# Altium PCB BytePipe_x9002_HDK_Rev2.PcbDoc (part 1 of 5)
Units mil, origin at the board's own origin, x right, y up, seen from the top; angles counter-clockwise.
Board outline 4250 x 4250 mil, 8 copper layers (Top Layer, L2-GND, L3-SIG, L4-GND, L5-PWR, L6-SIG, L7-GND, Bottom Layer), stack 63 mil thick; 296 components, 250 nets, 1198 pads, 2326 vias.
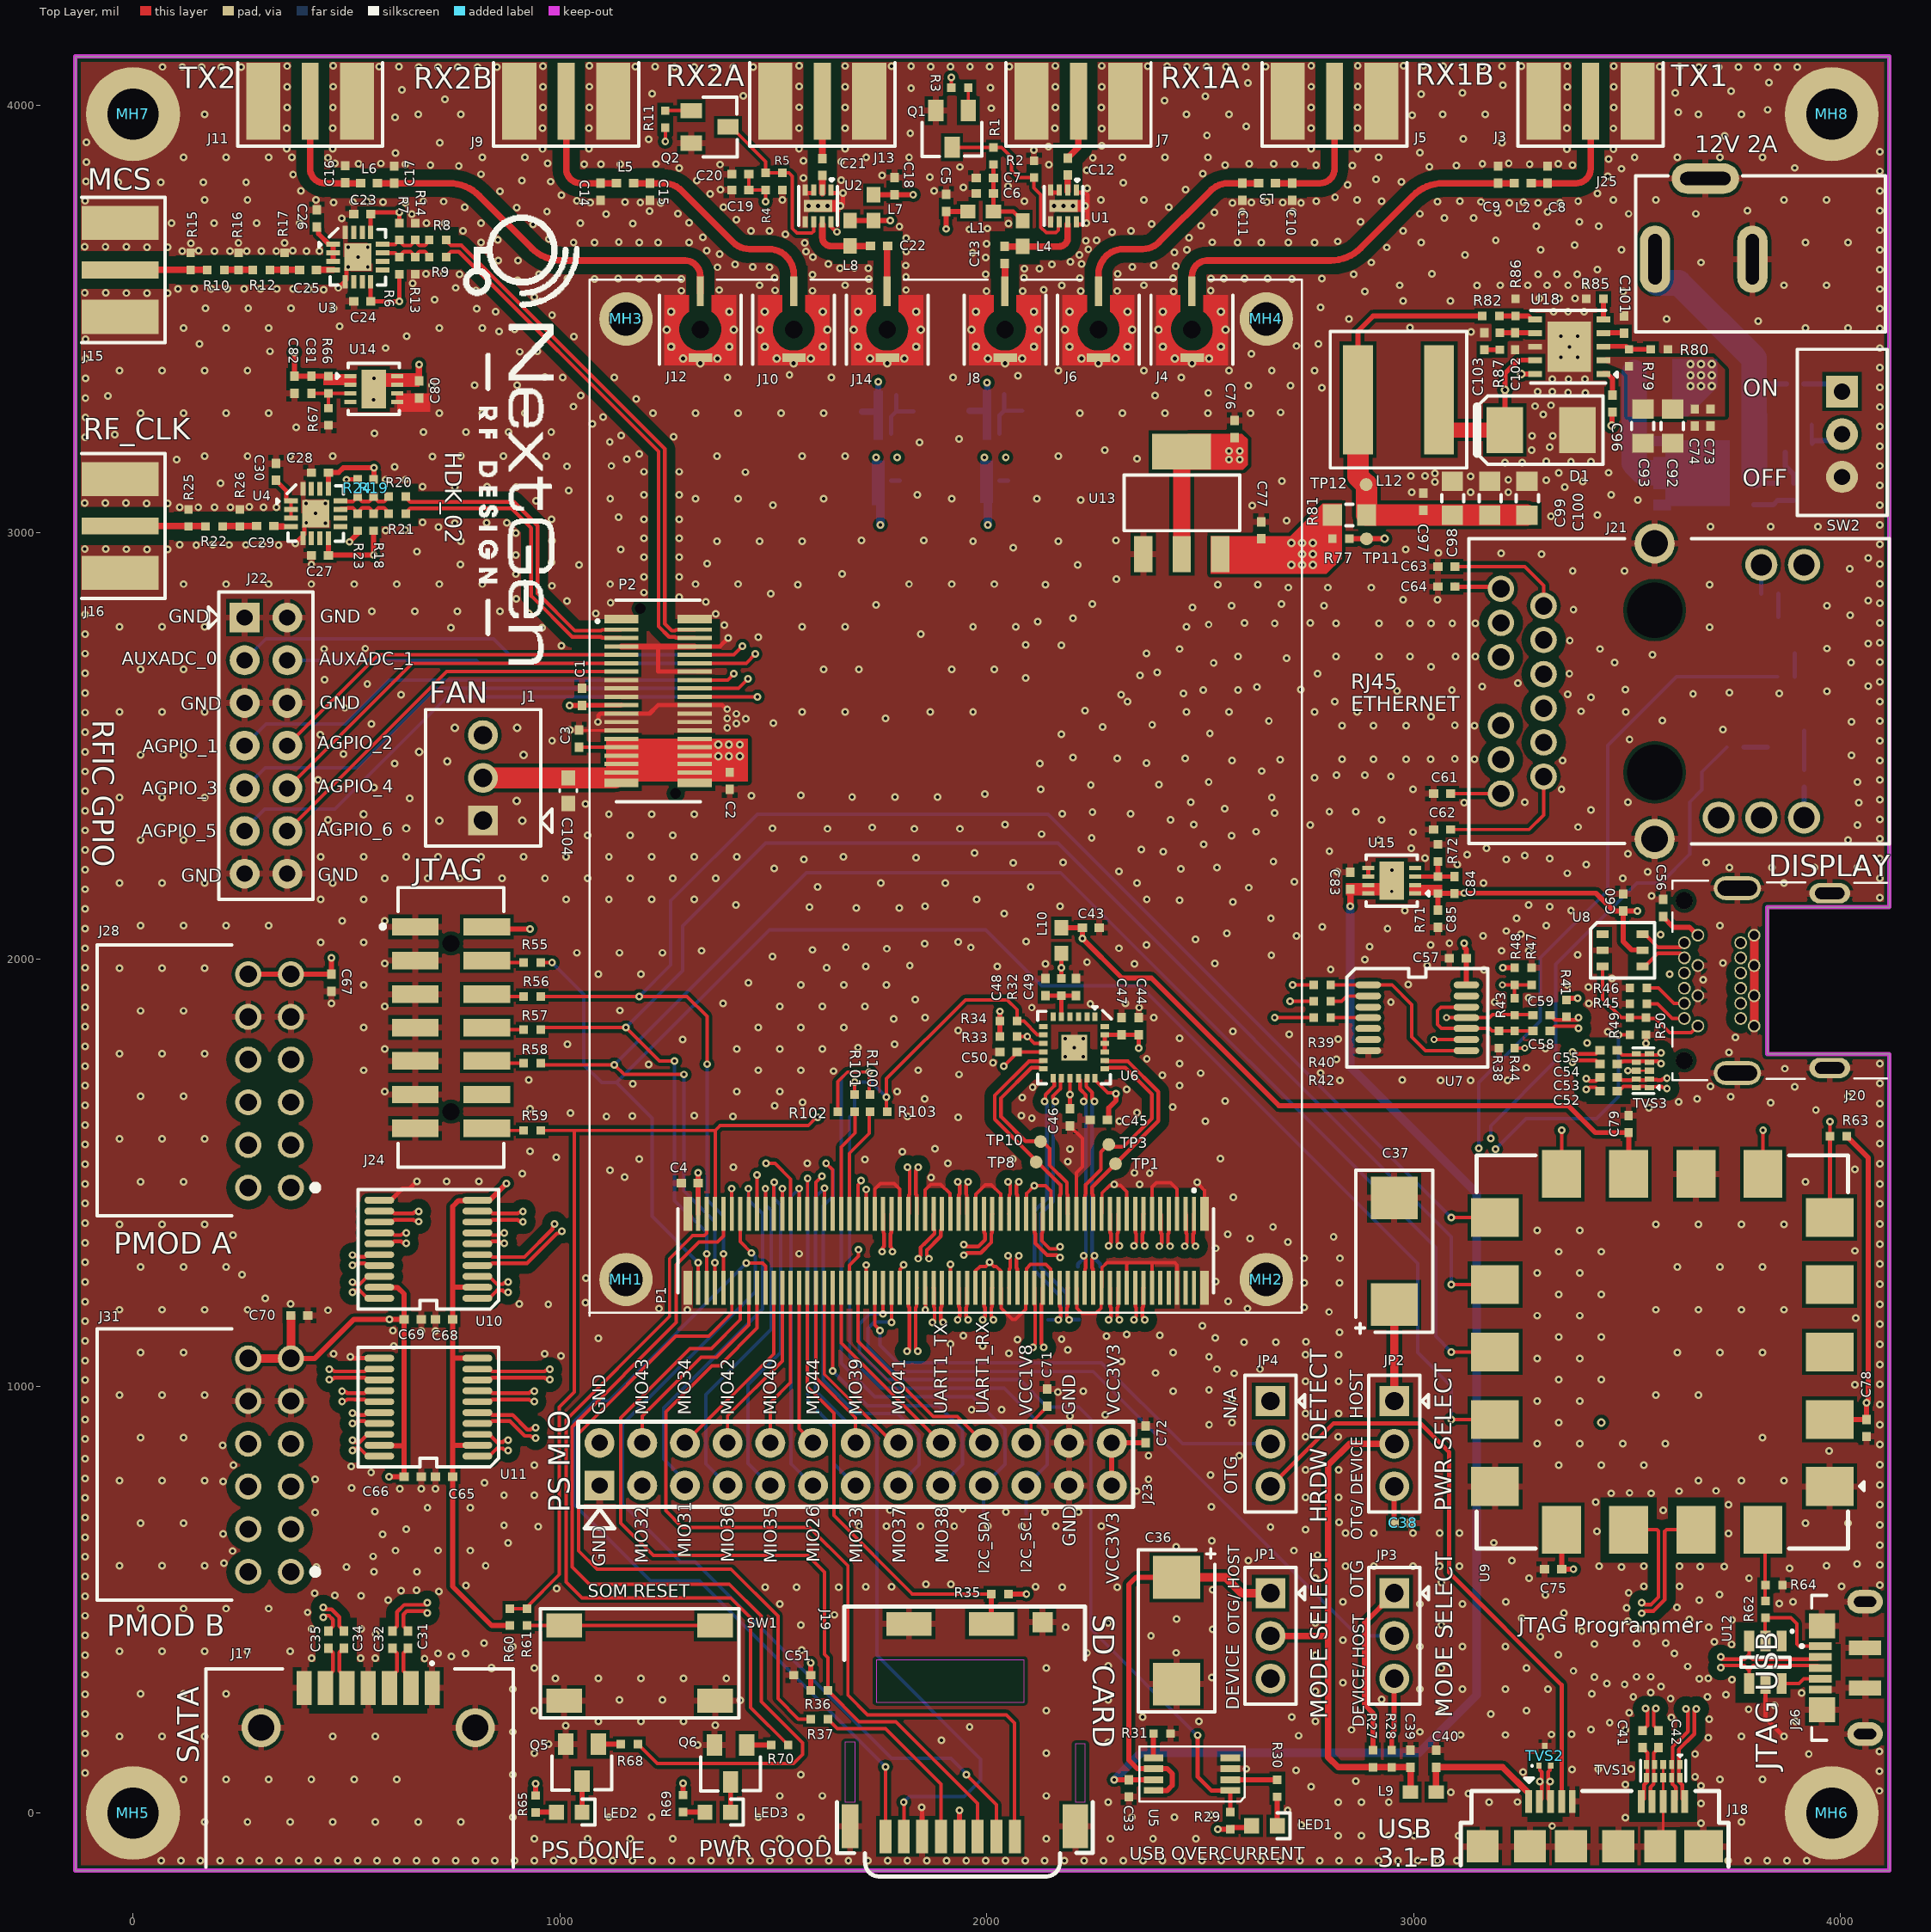
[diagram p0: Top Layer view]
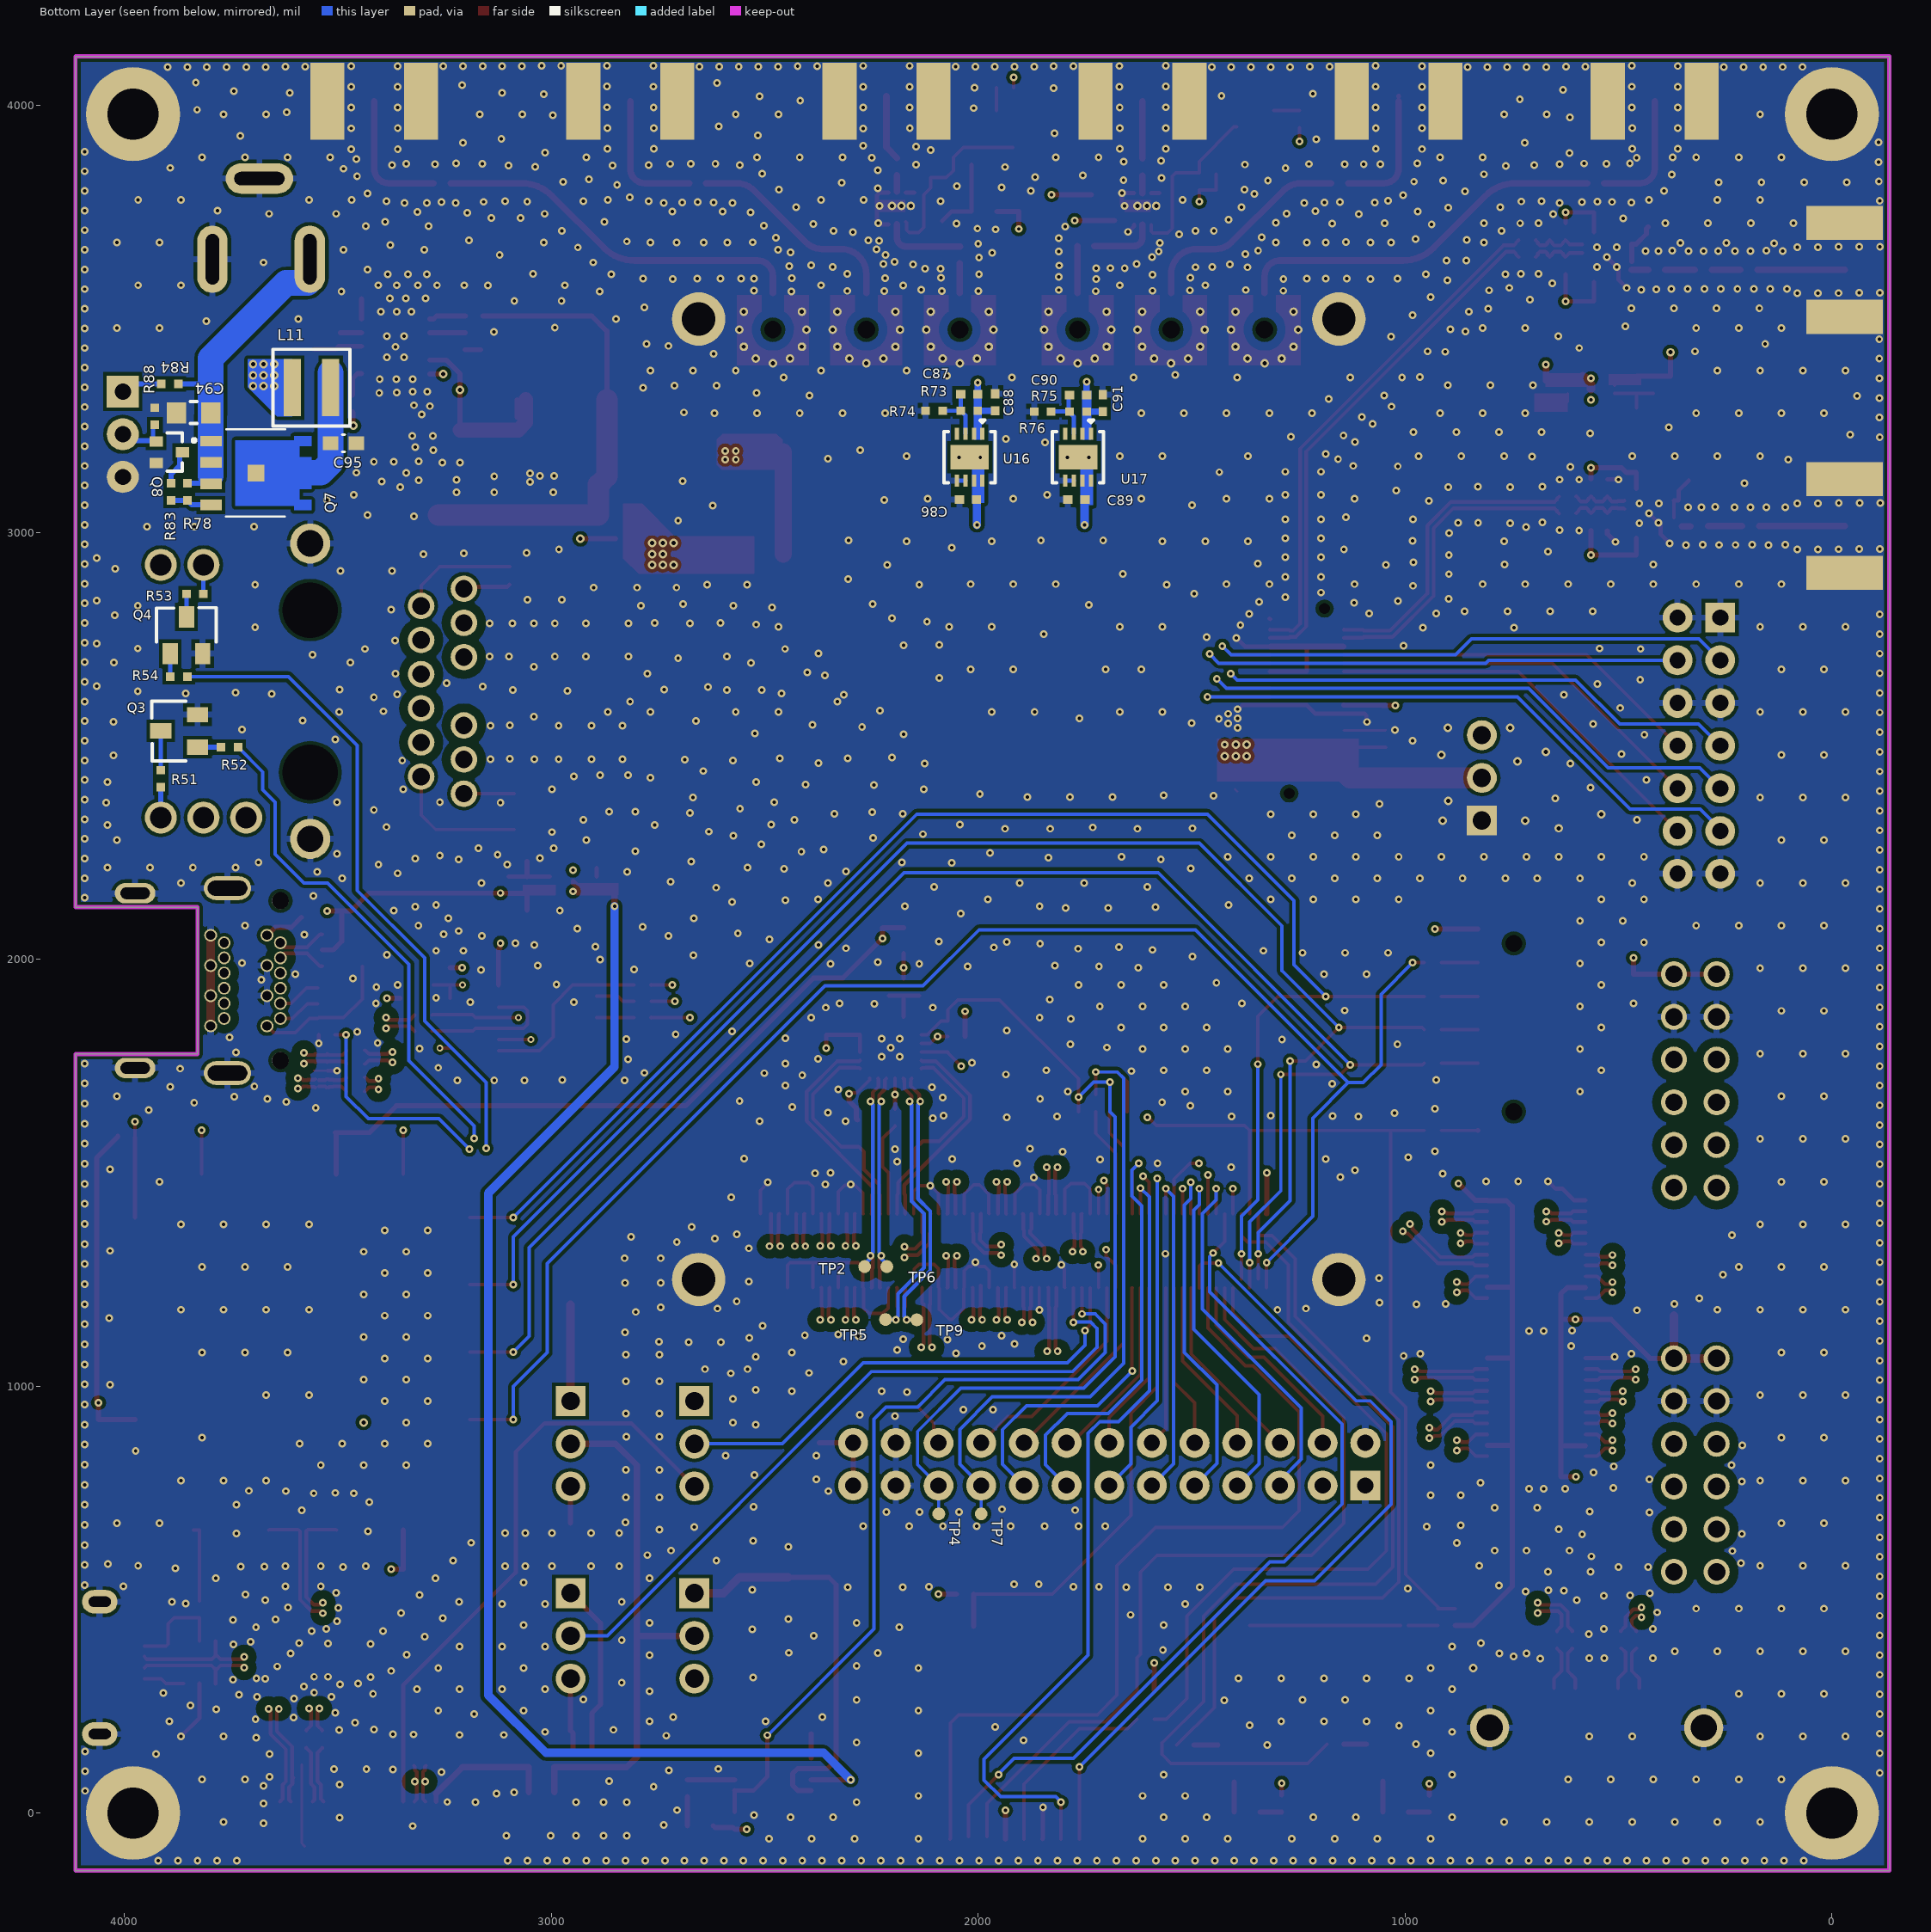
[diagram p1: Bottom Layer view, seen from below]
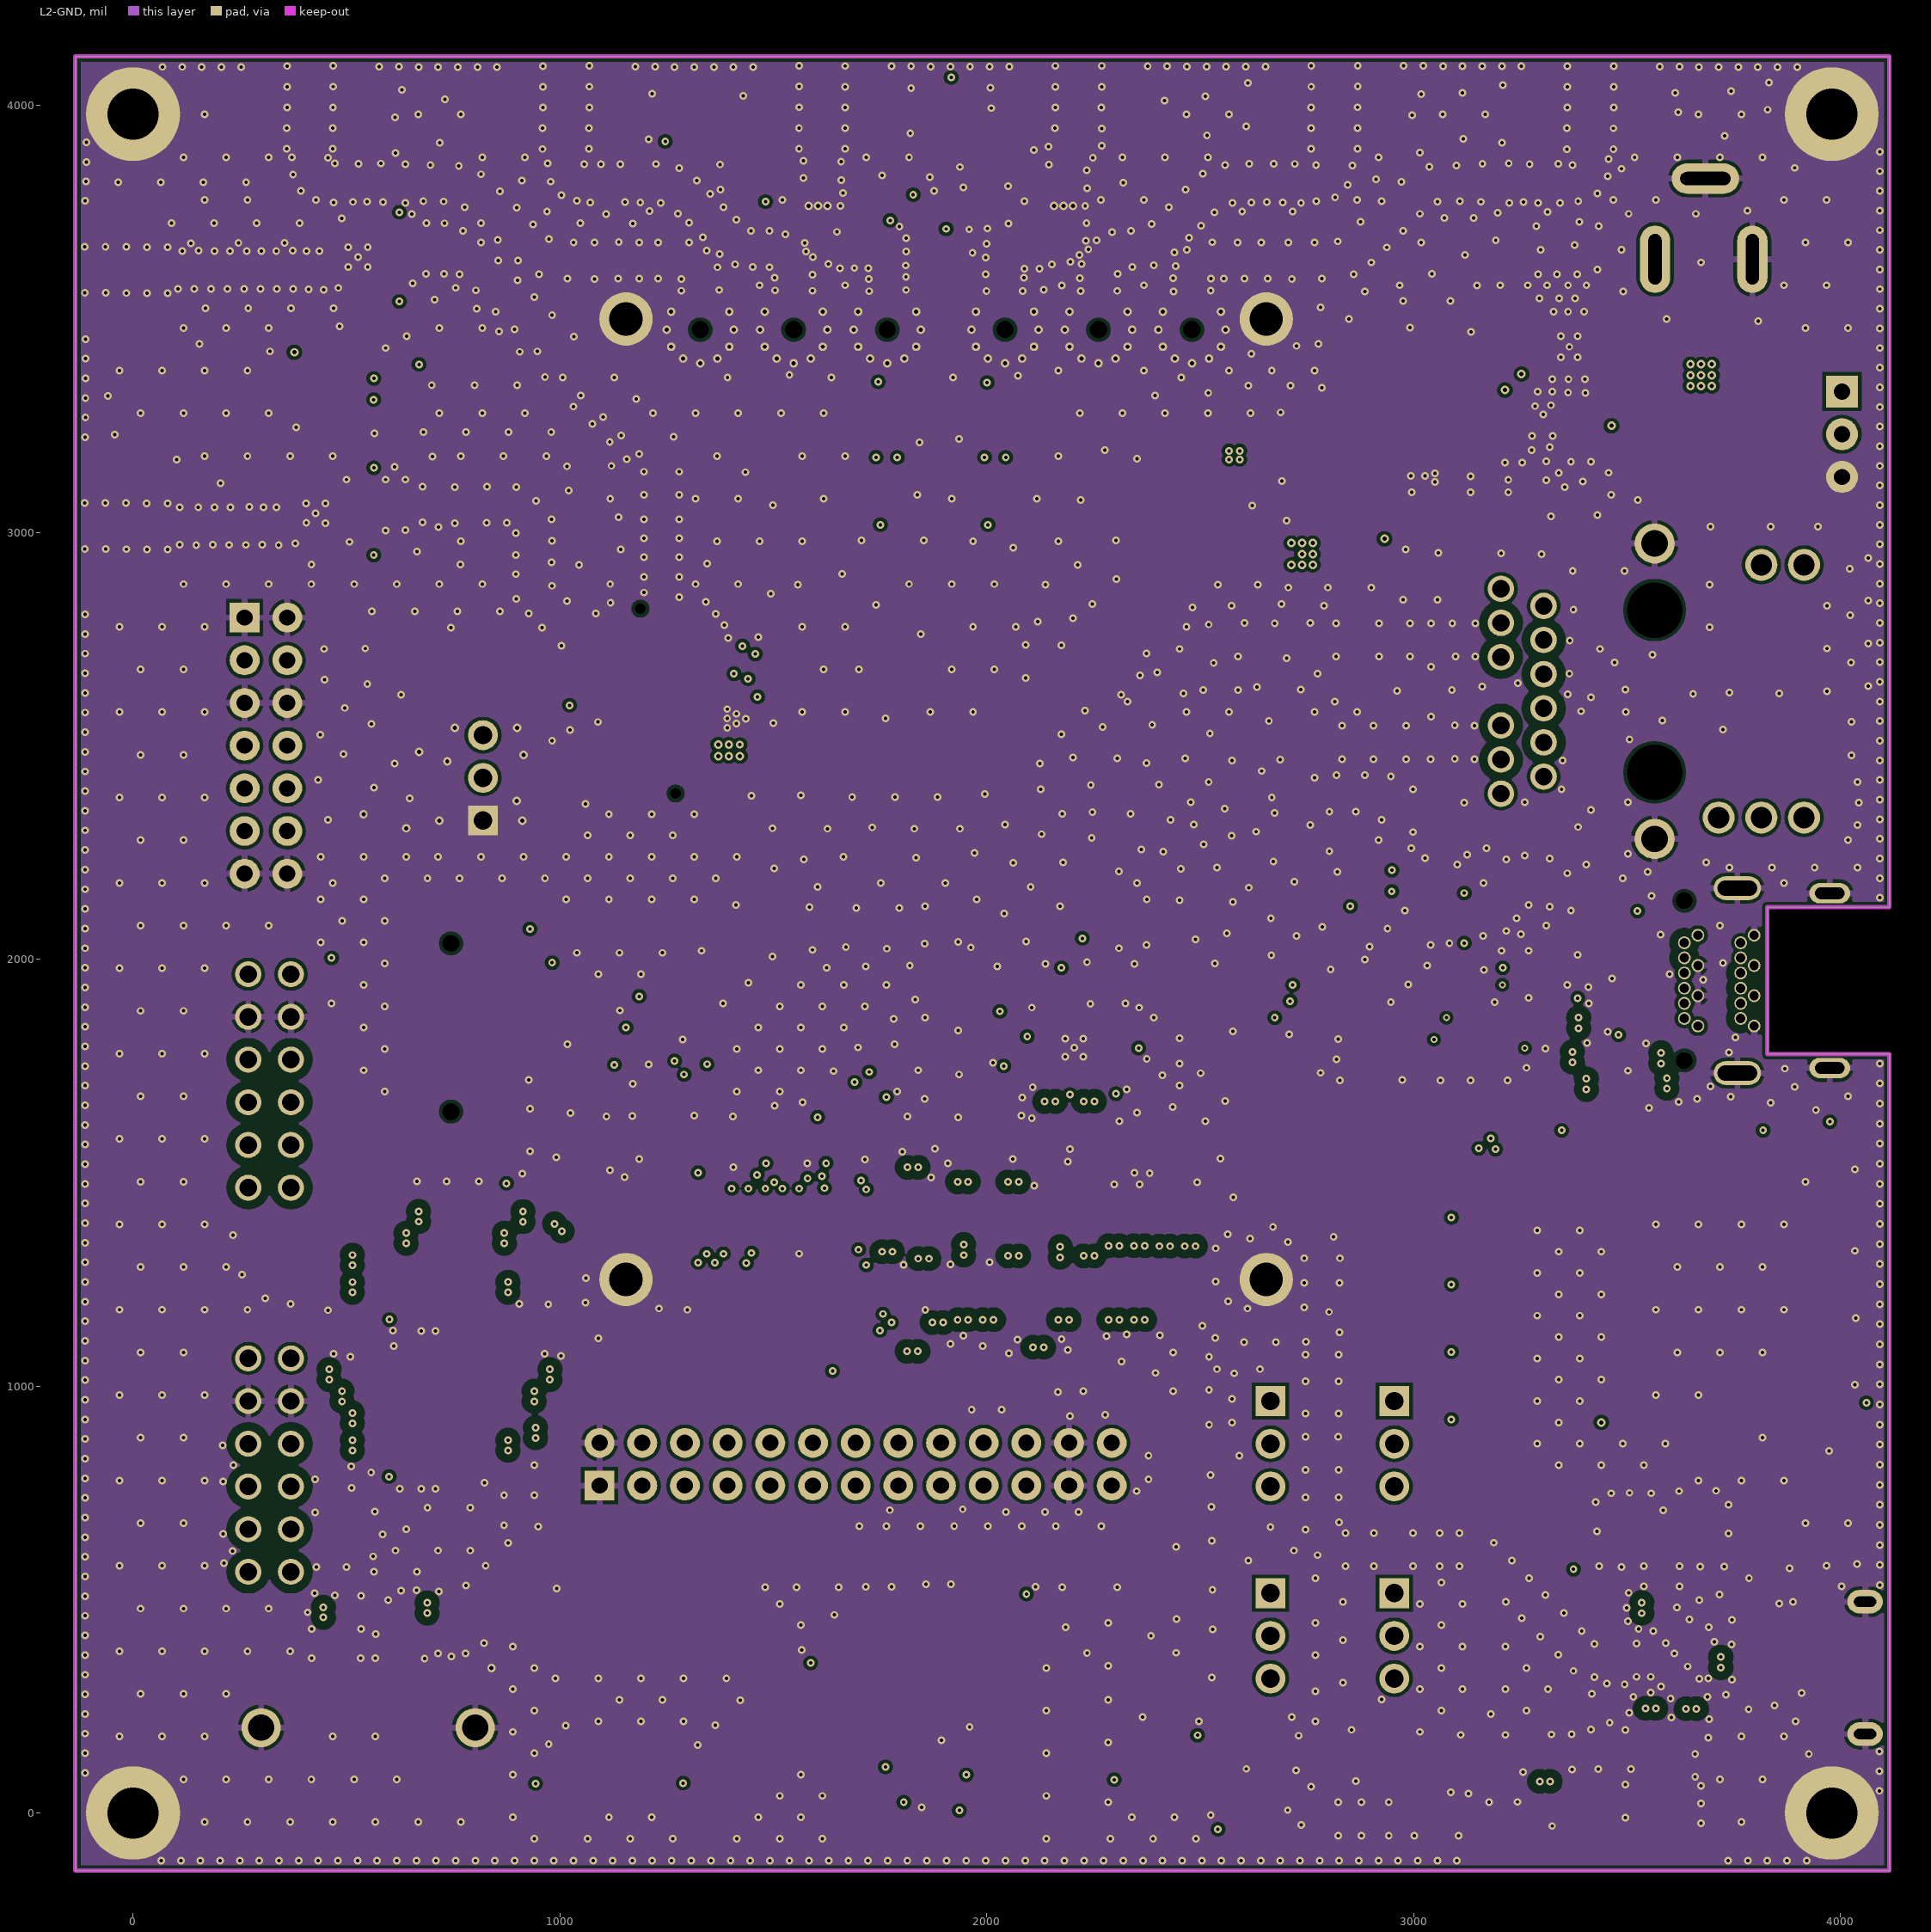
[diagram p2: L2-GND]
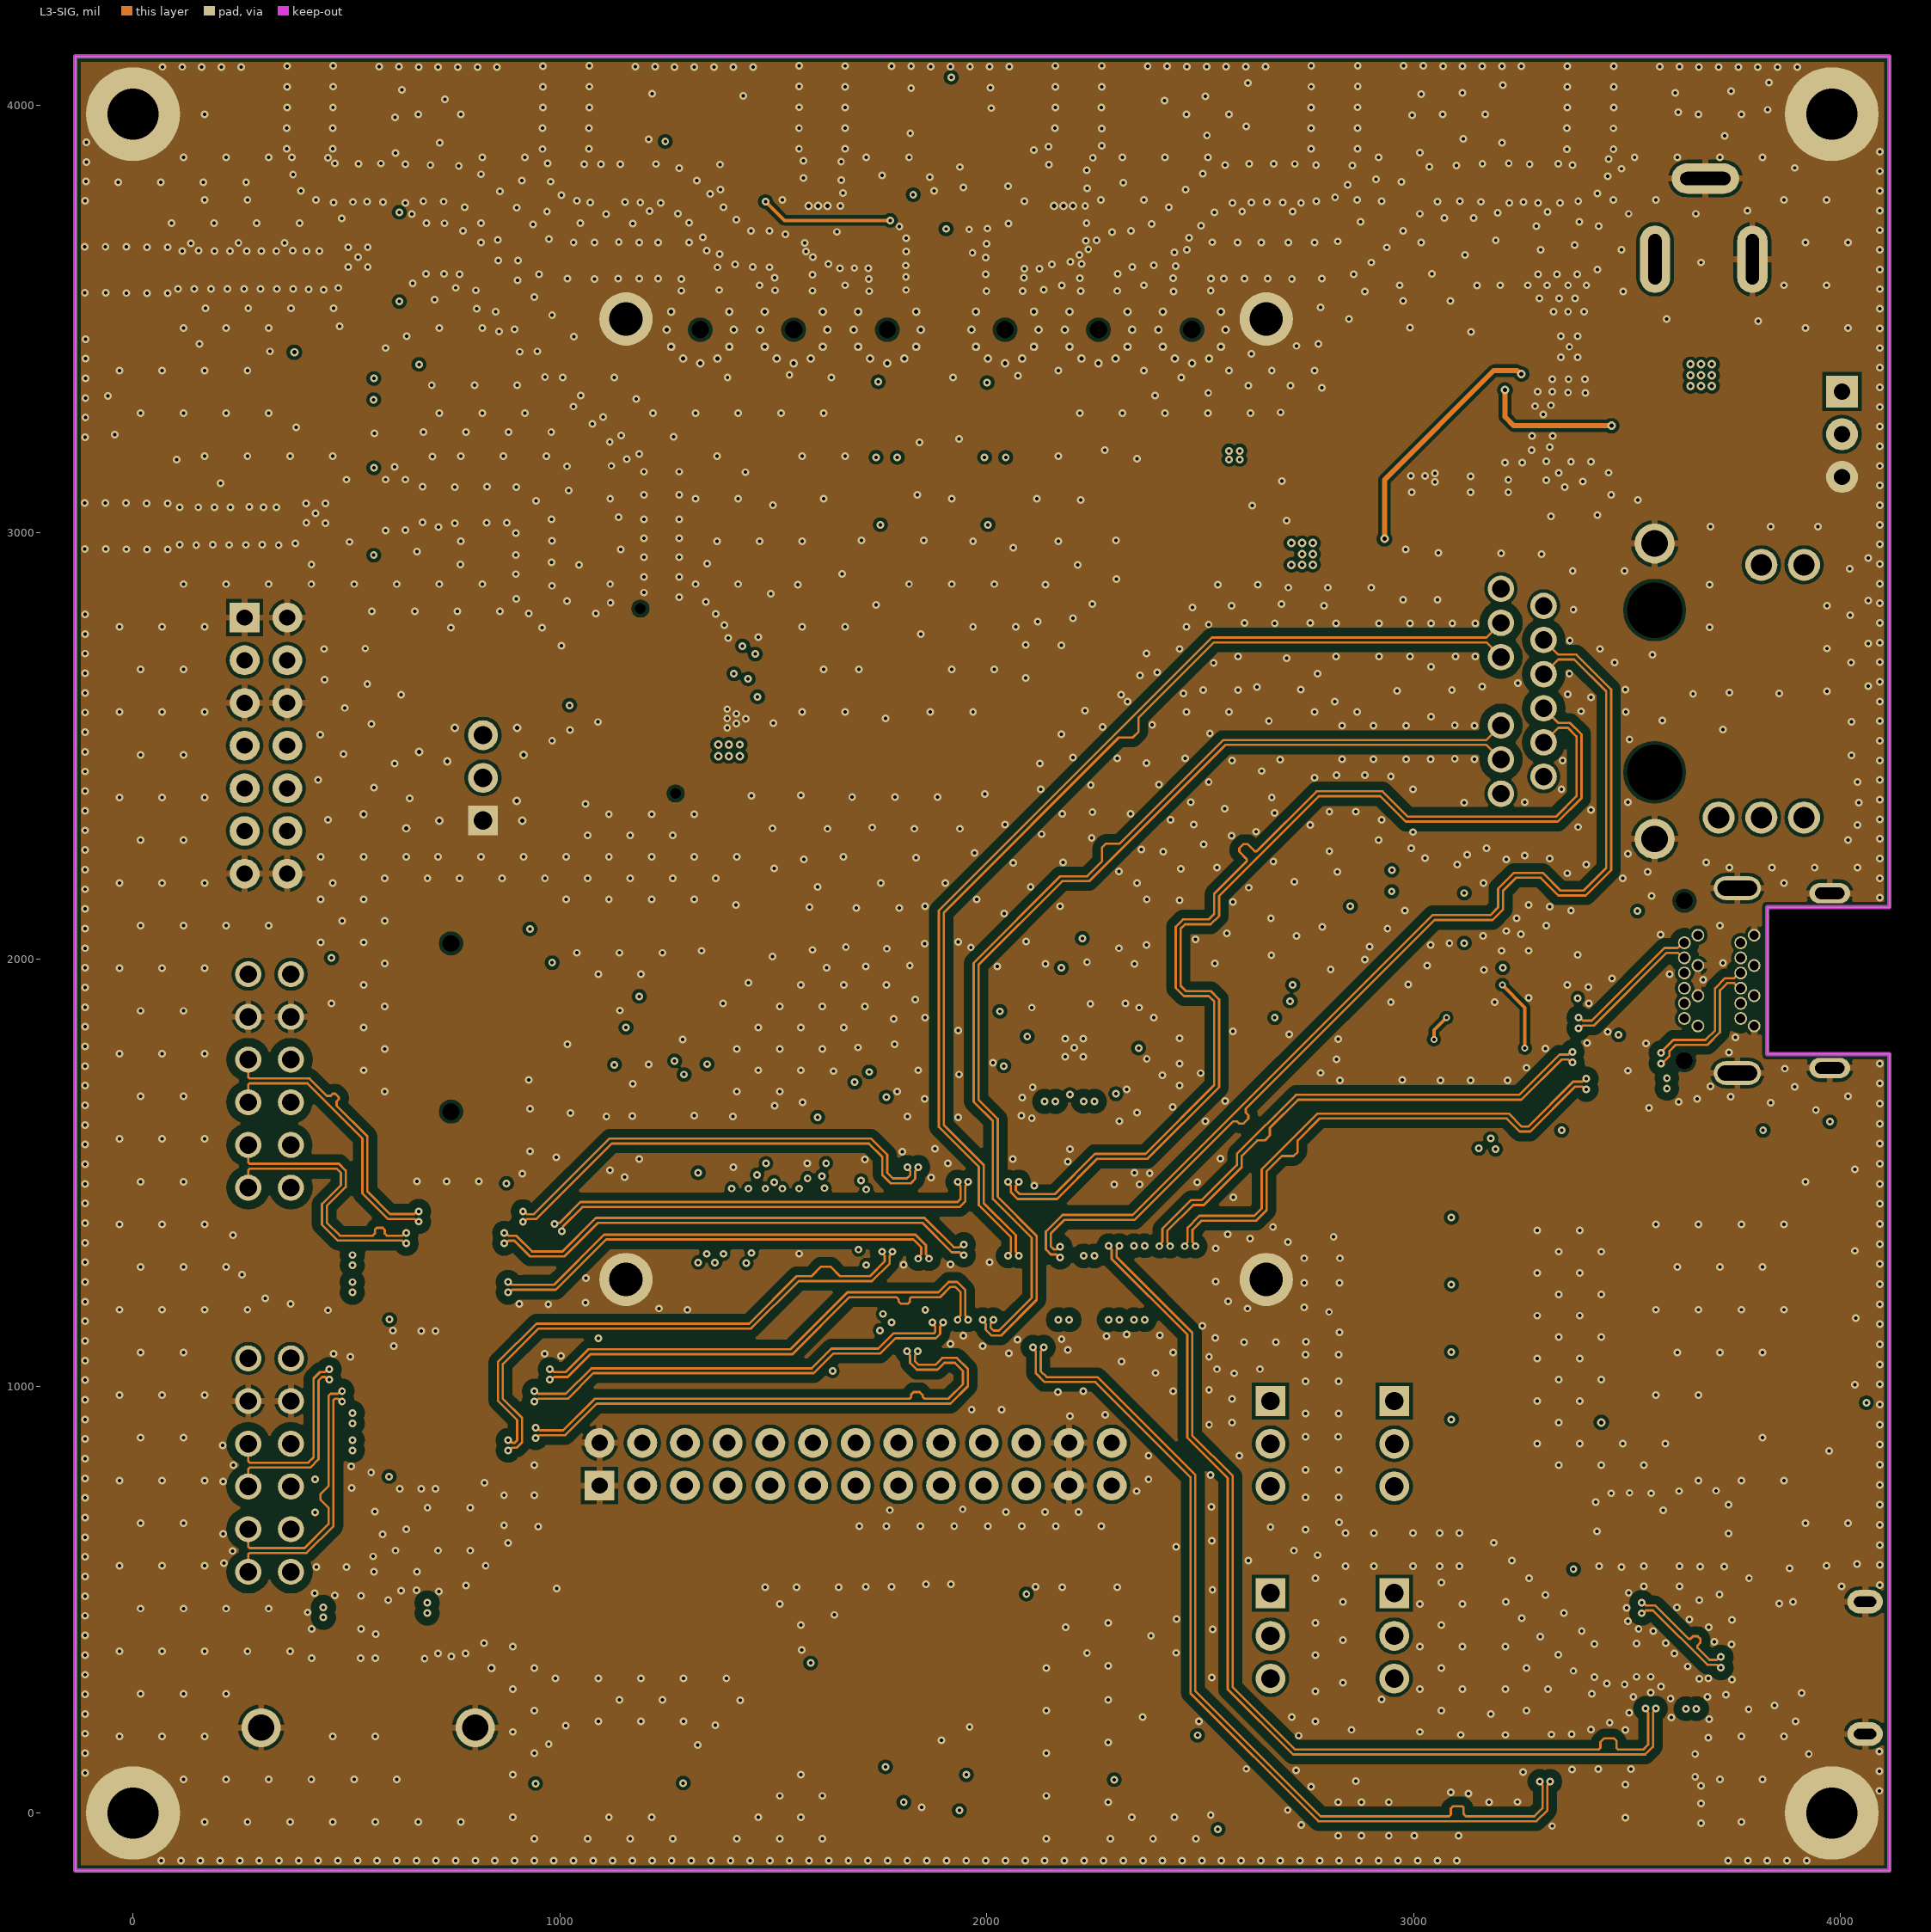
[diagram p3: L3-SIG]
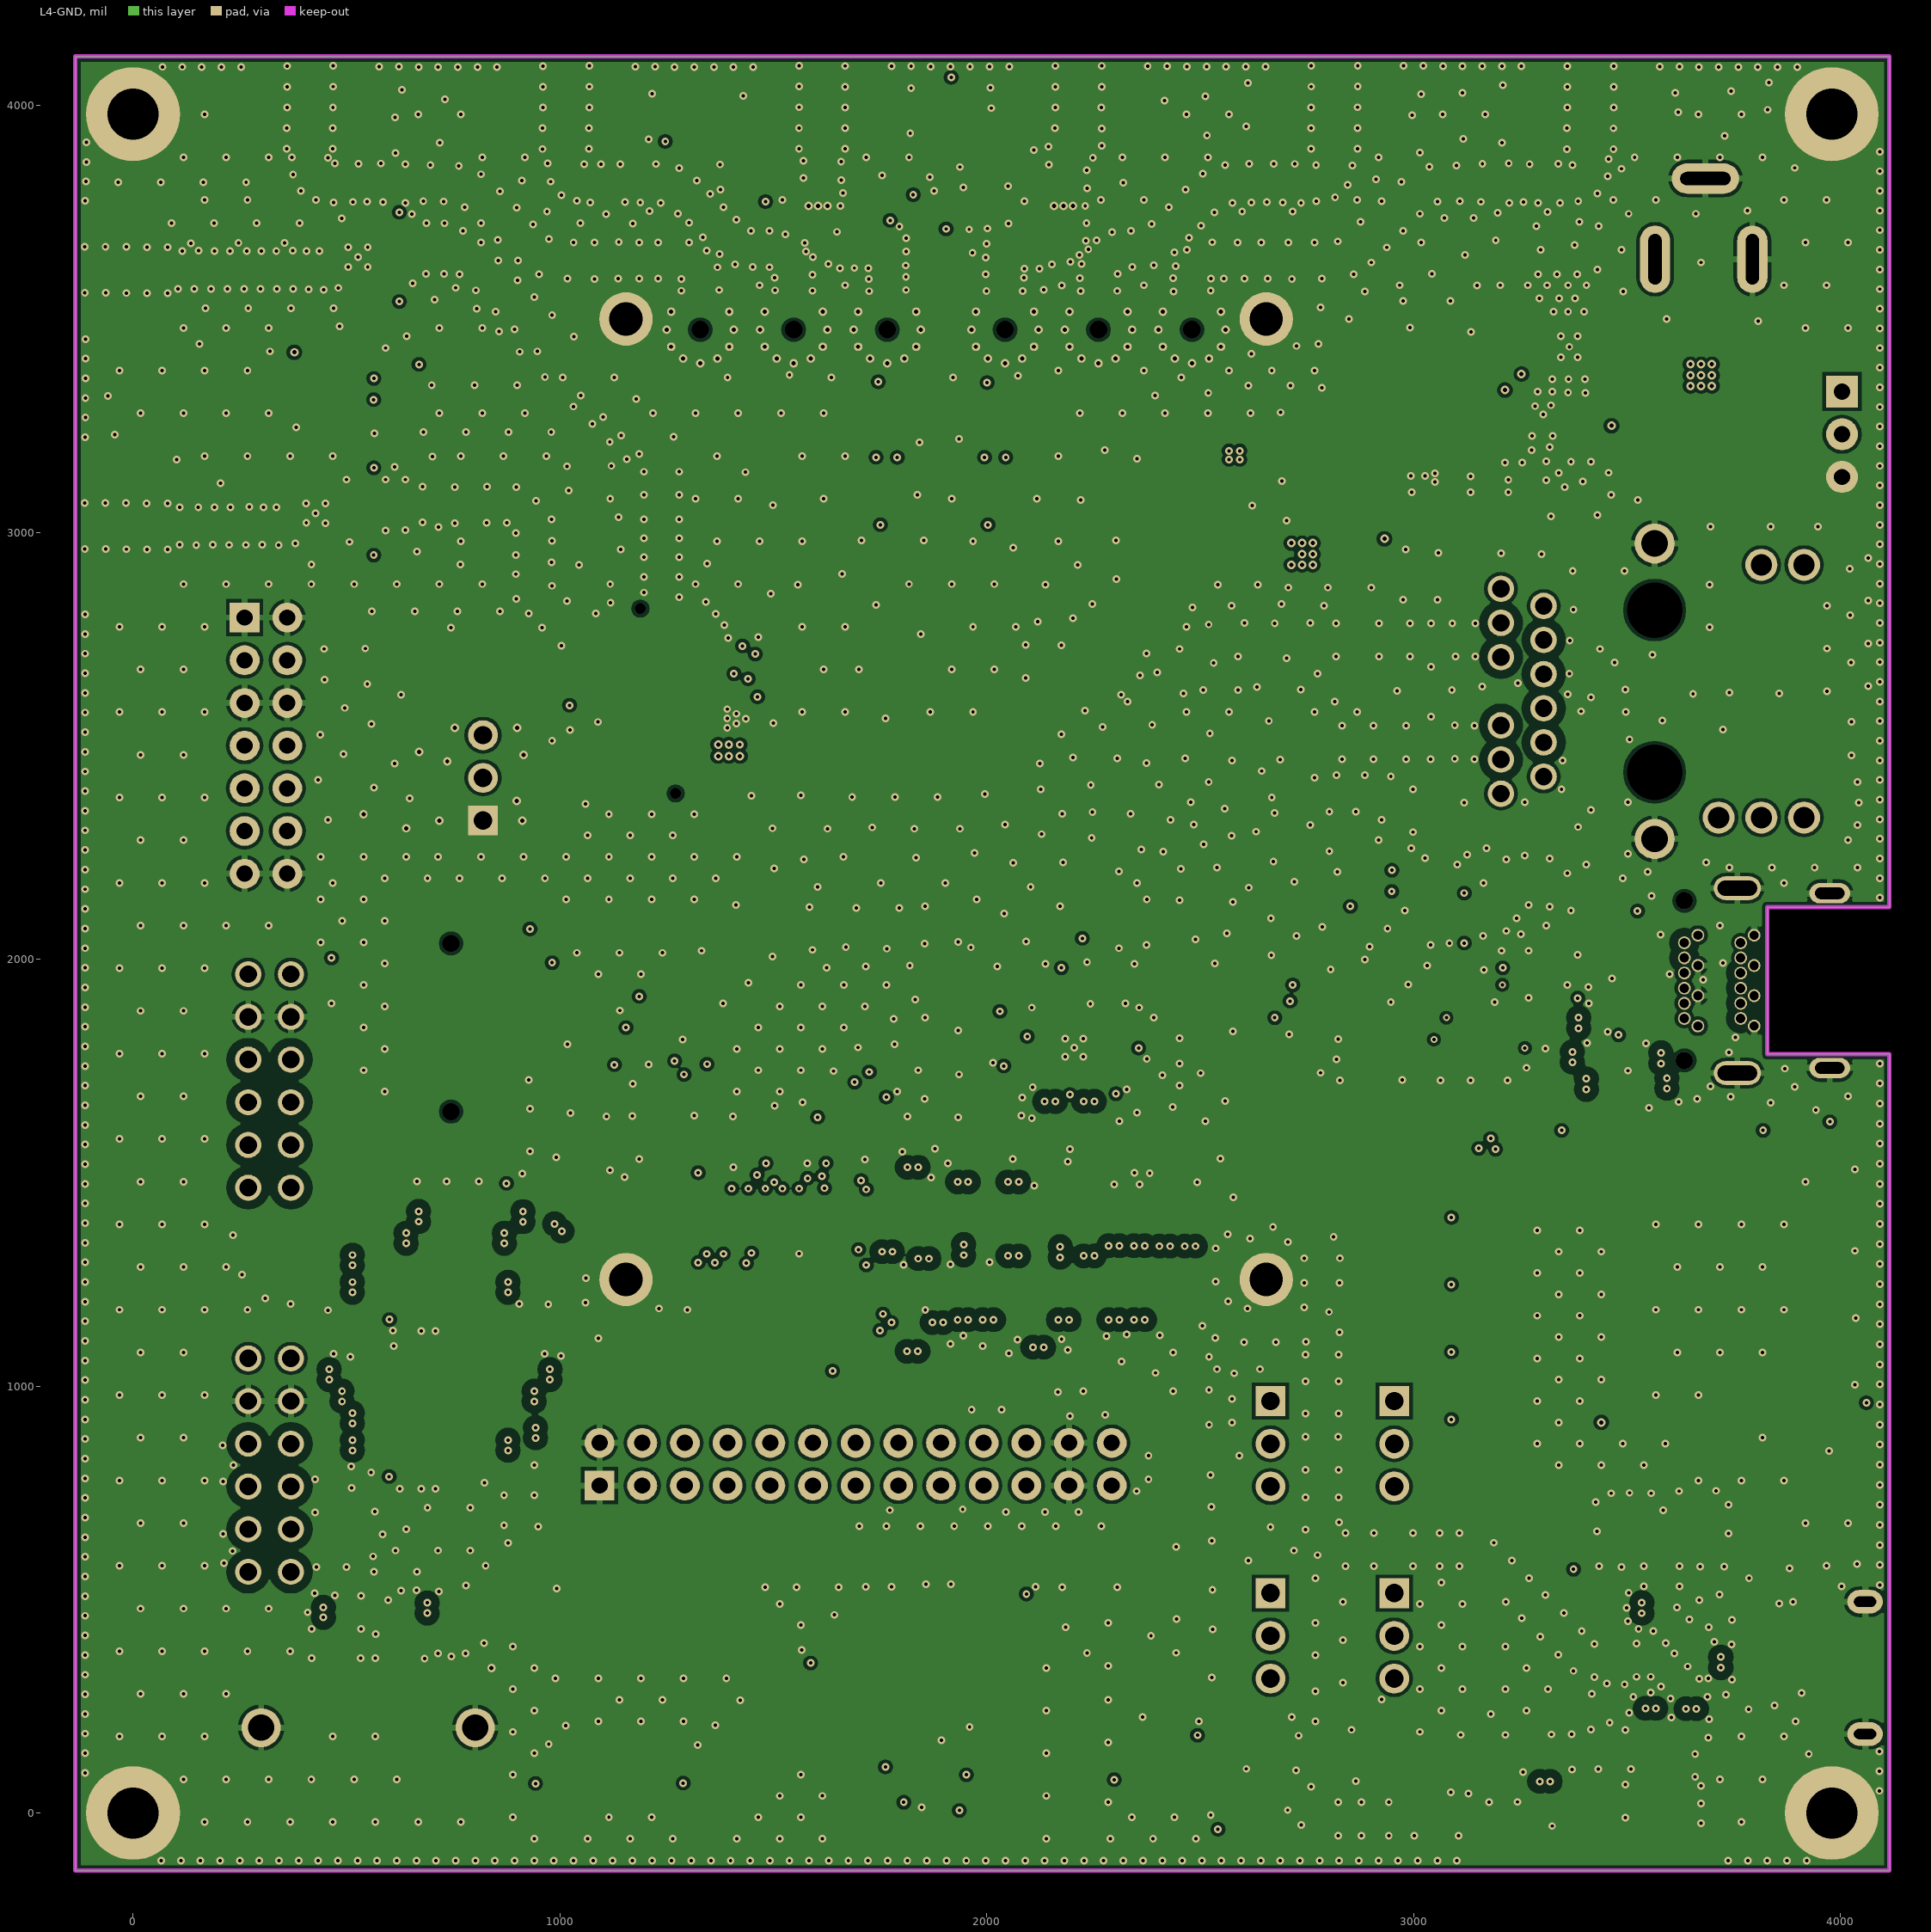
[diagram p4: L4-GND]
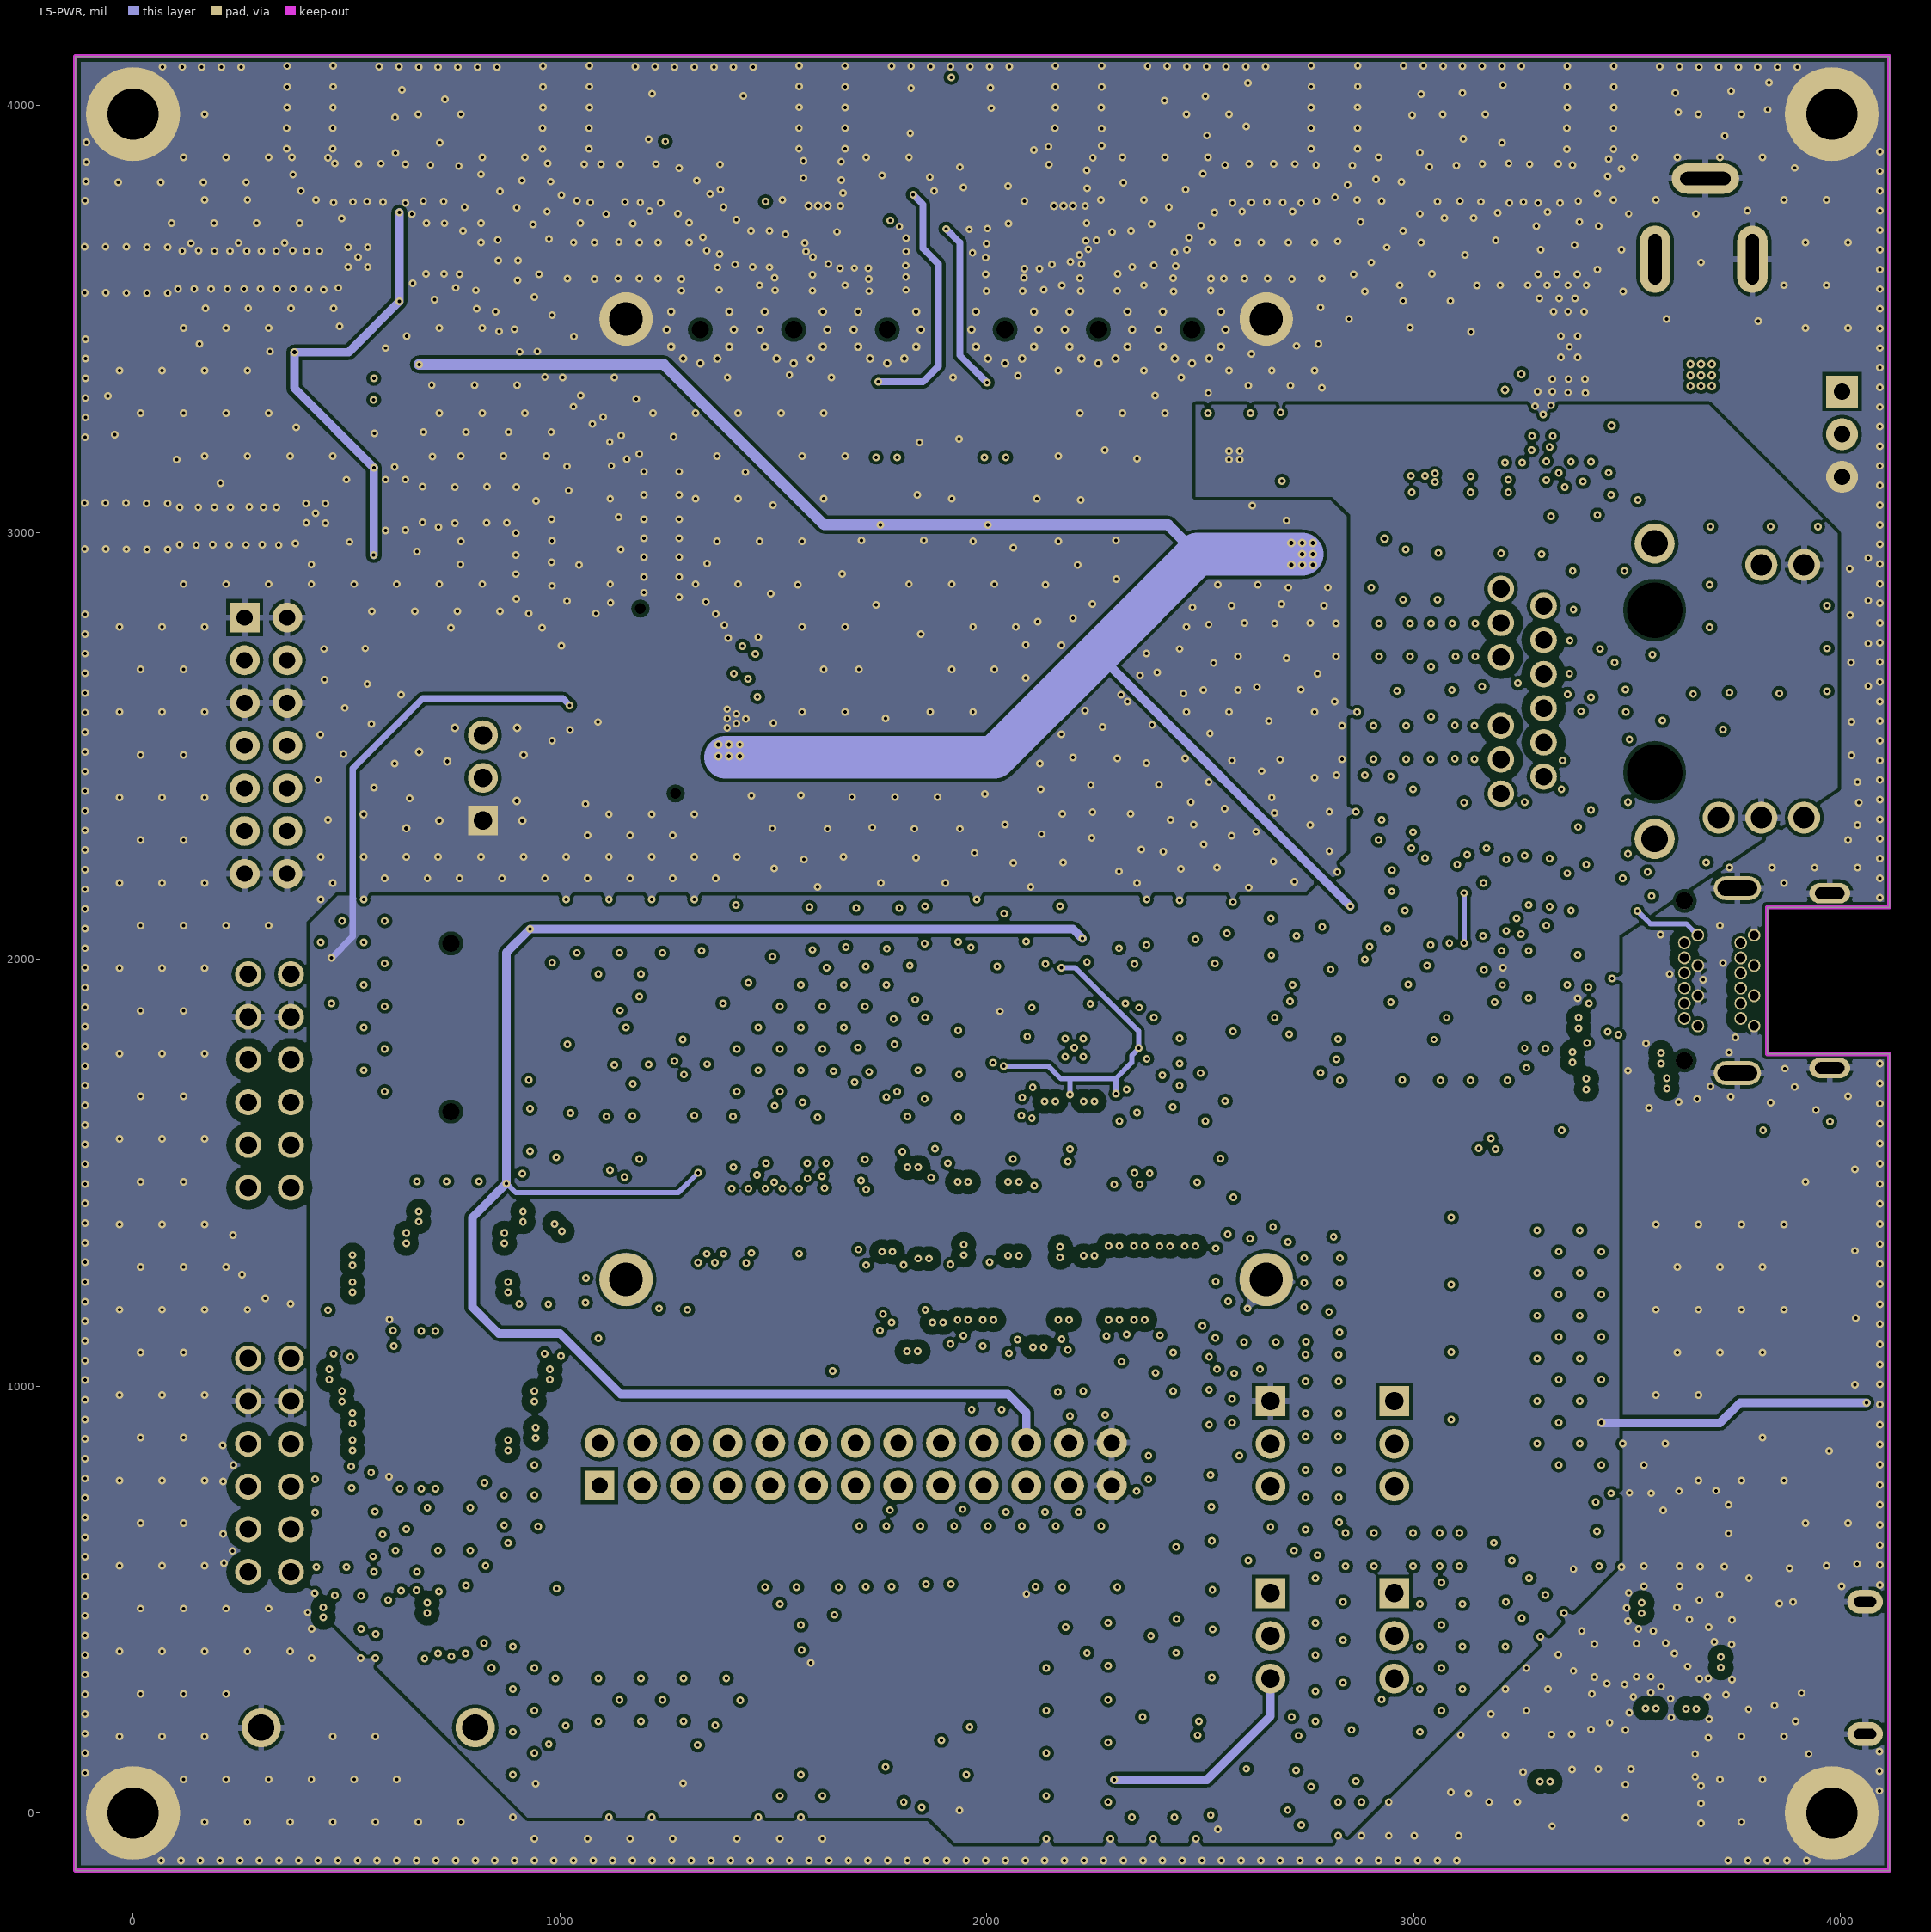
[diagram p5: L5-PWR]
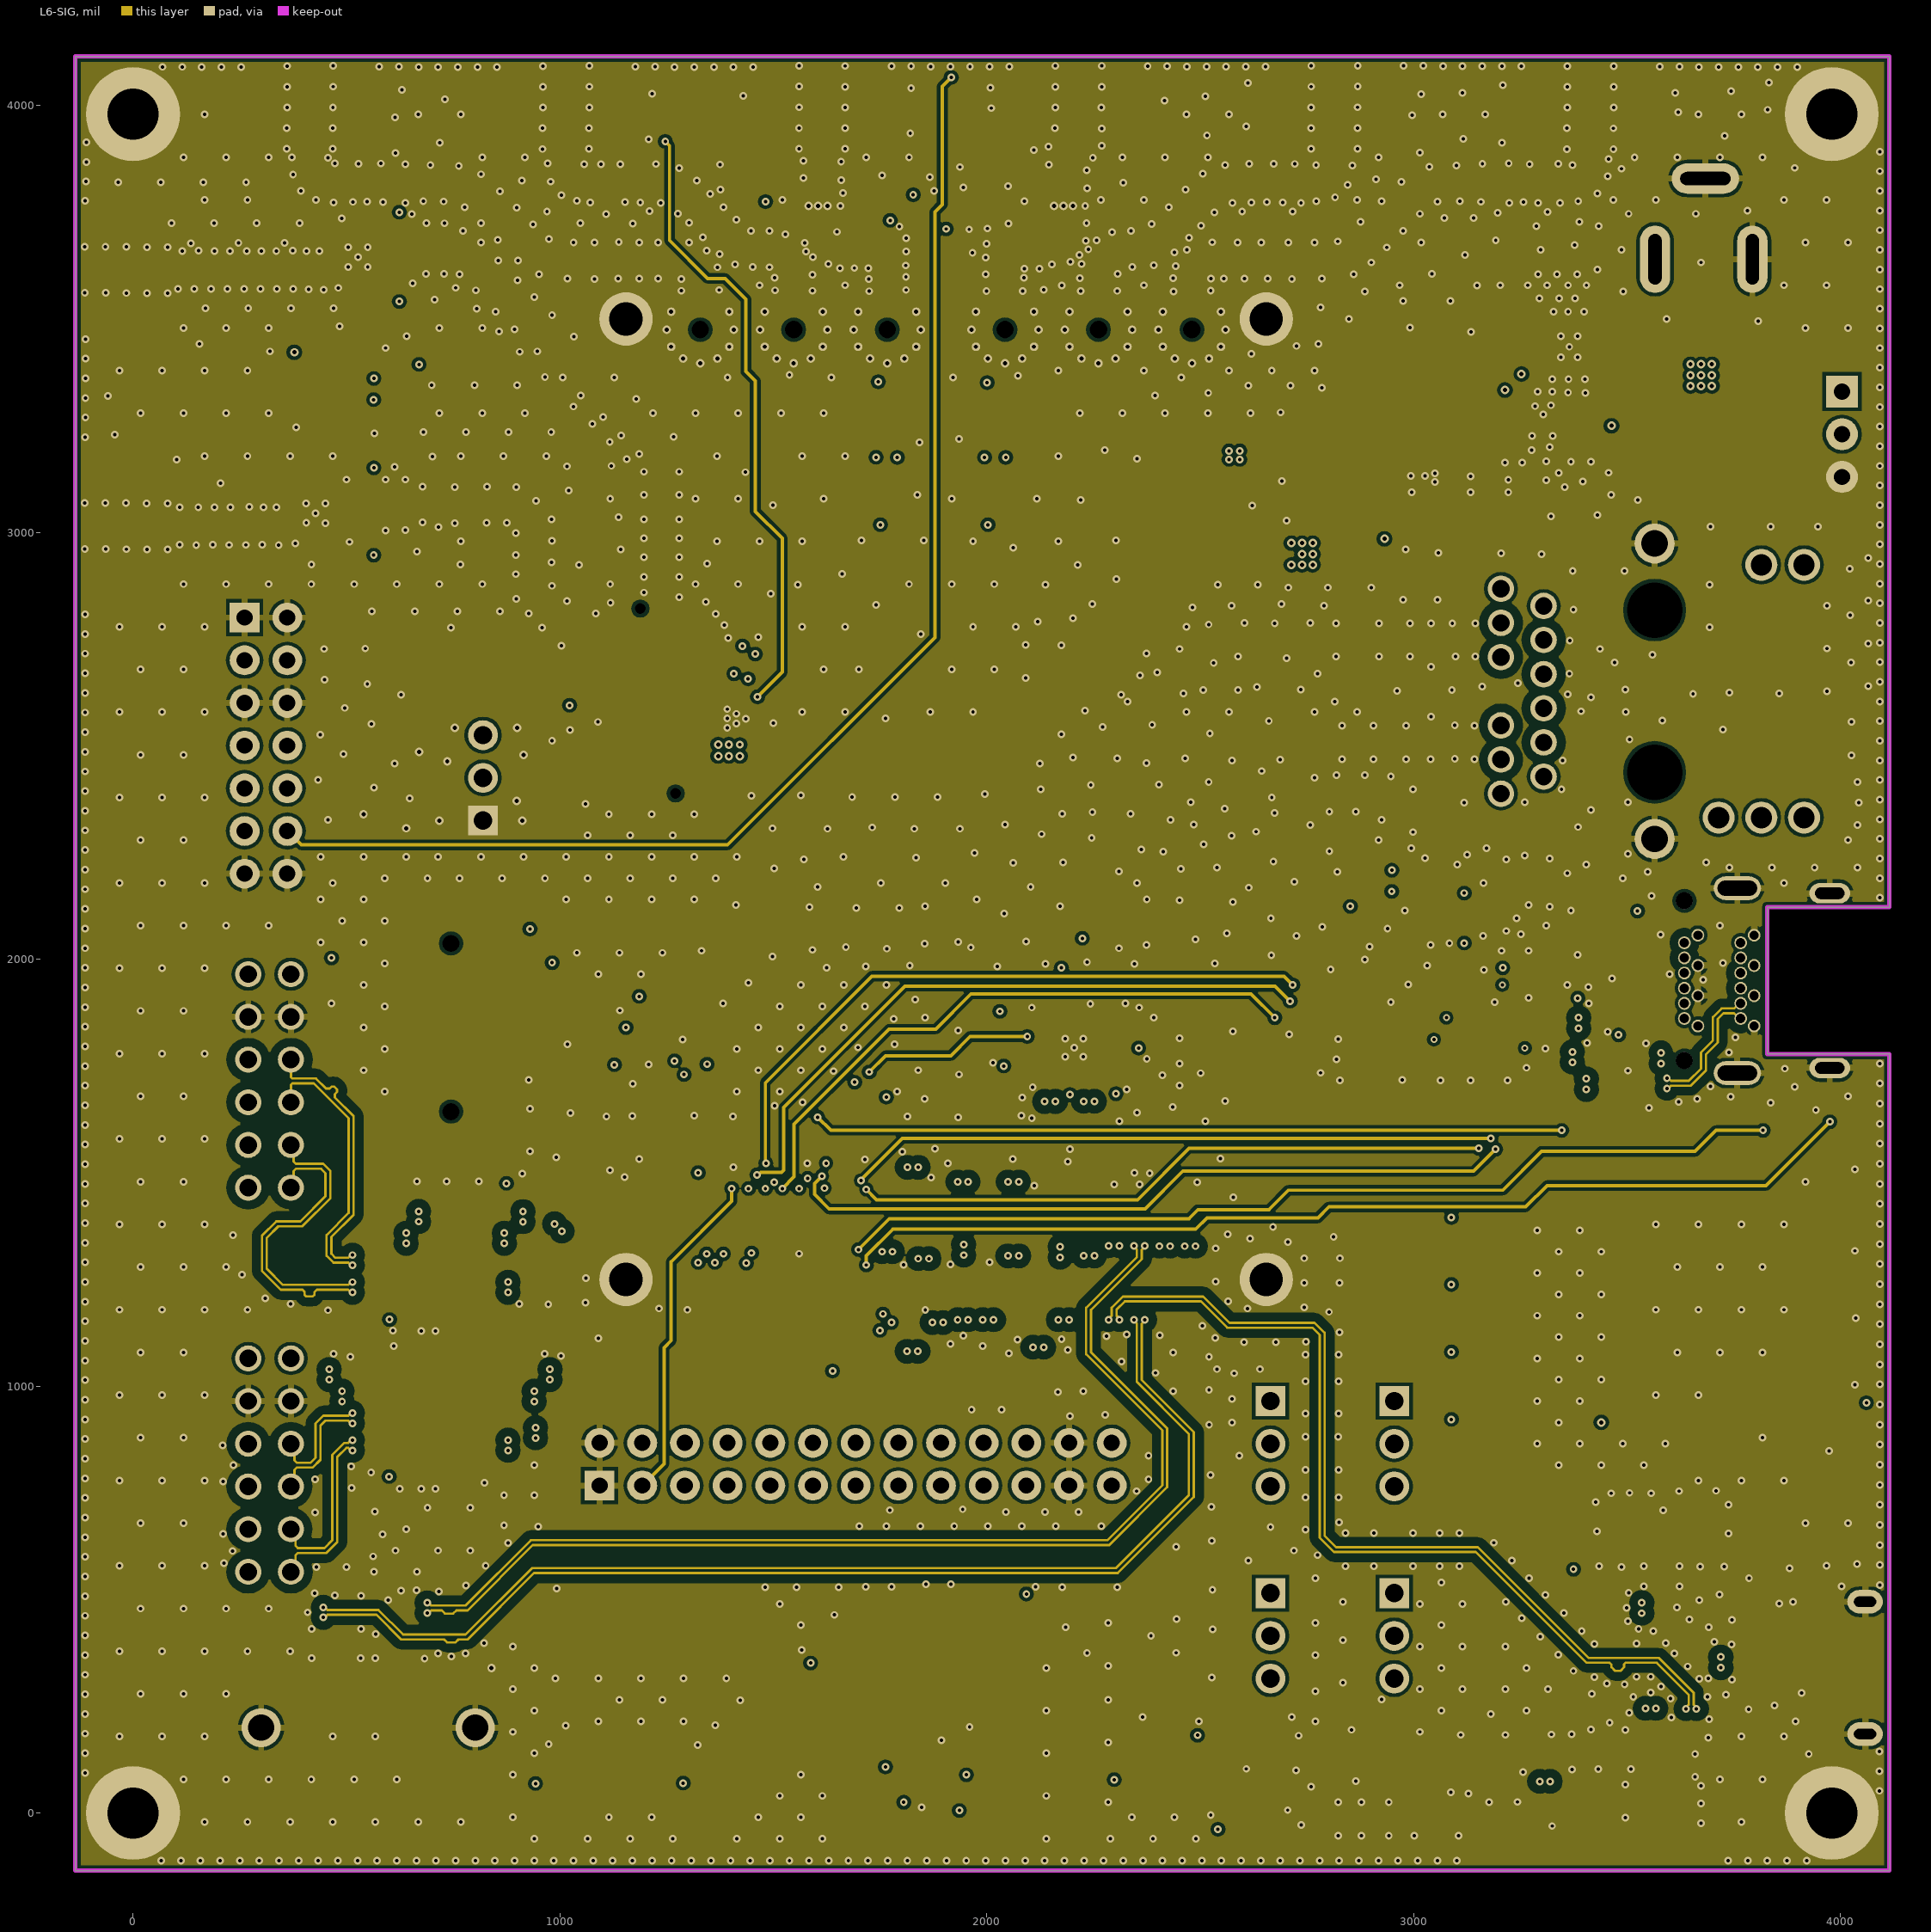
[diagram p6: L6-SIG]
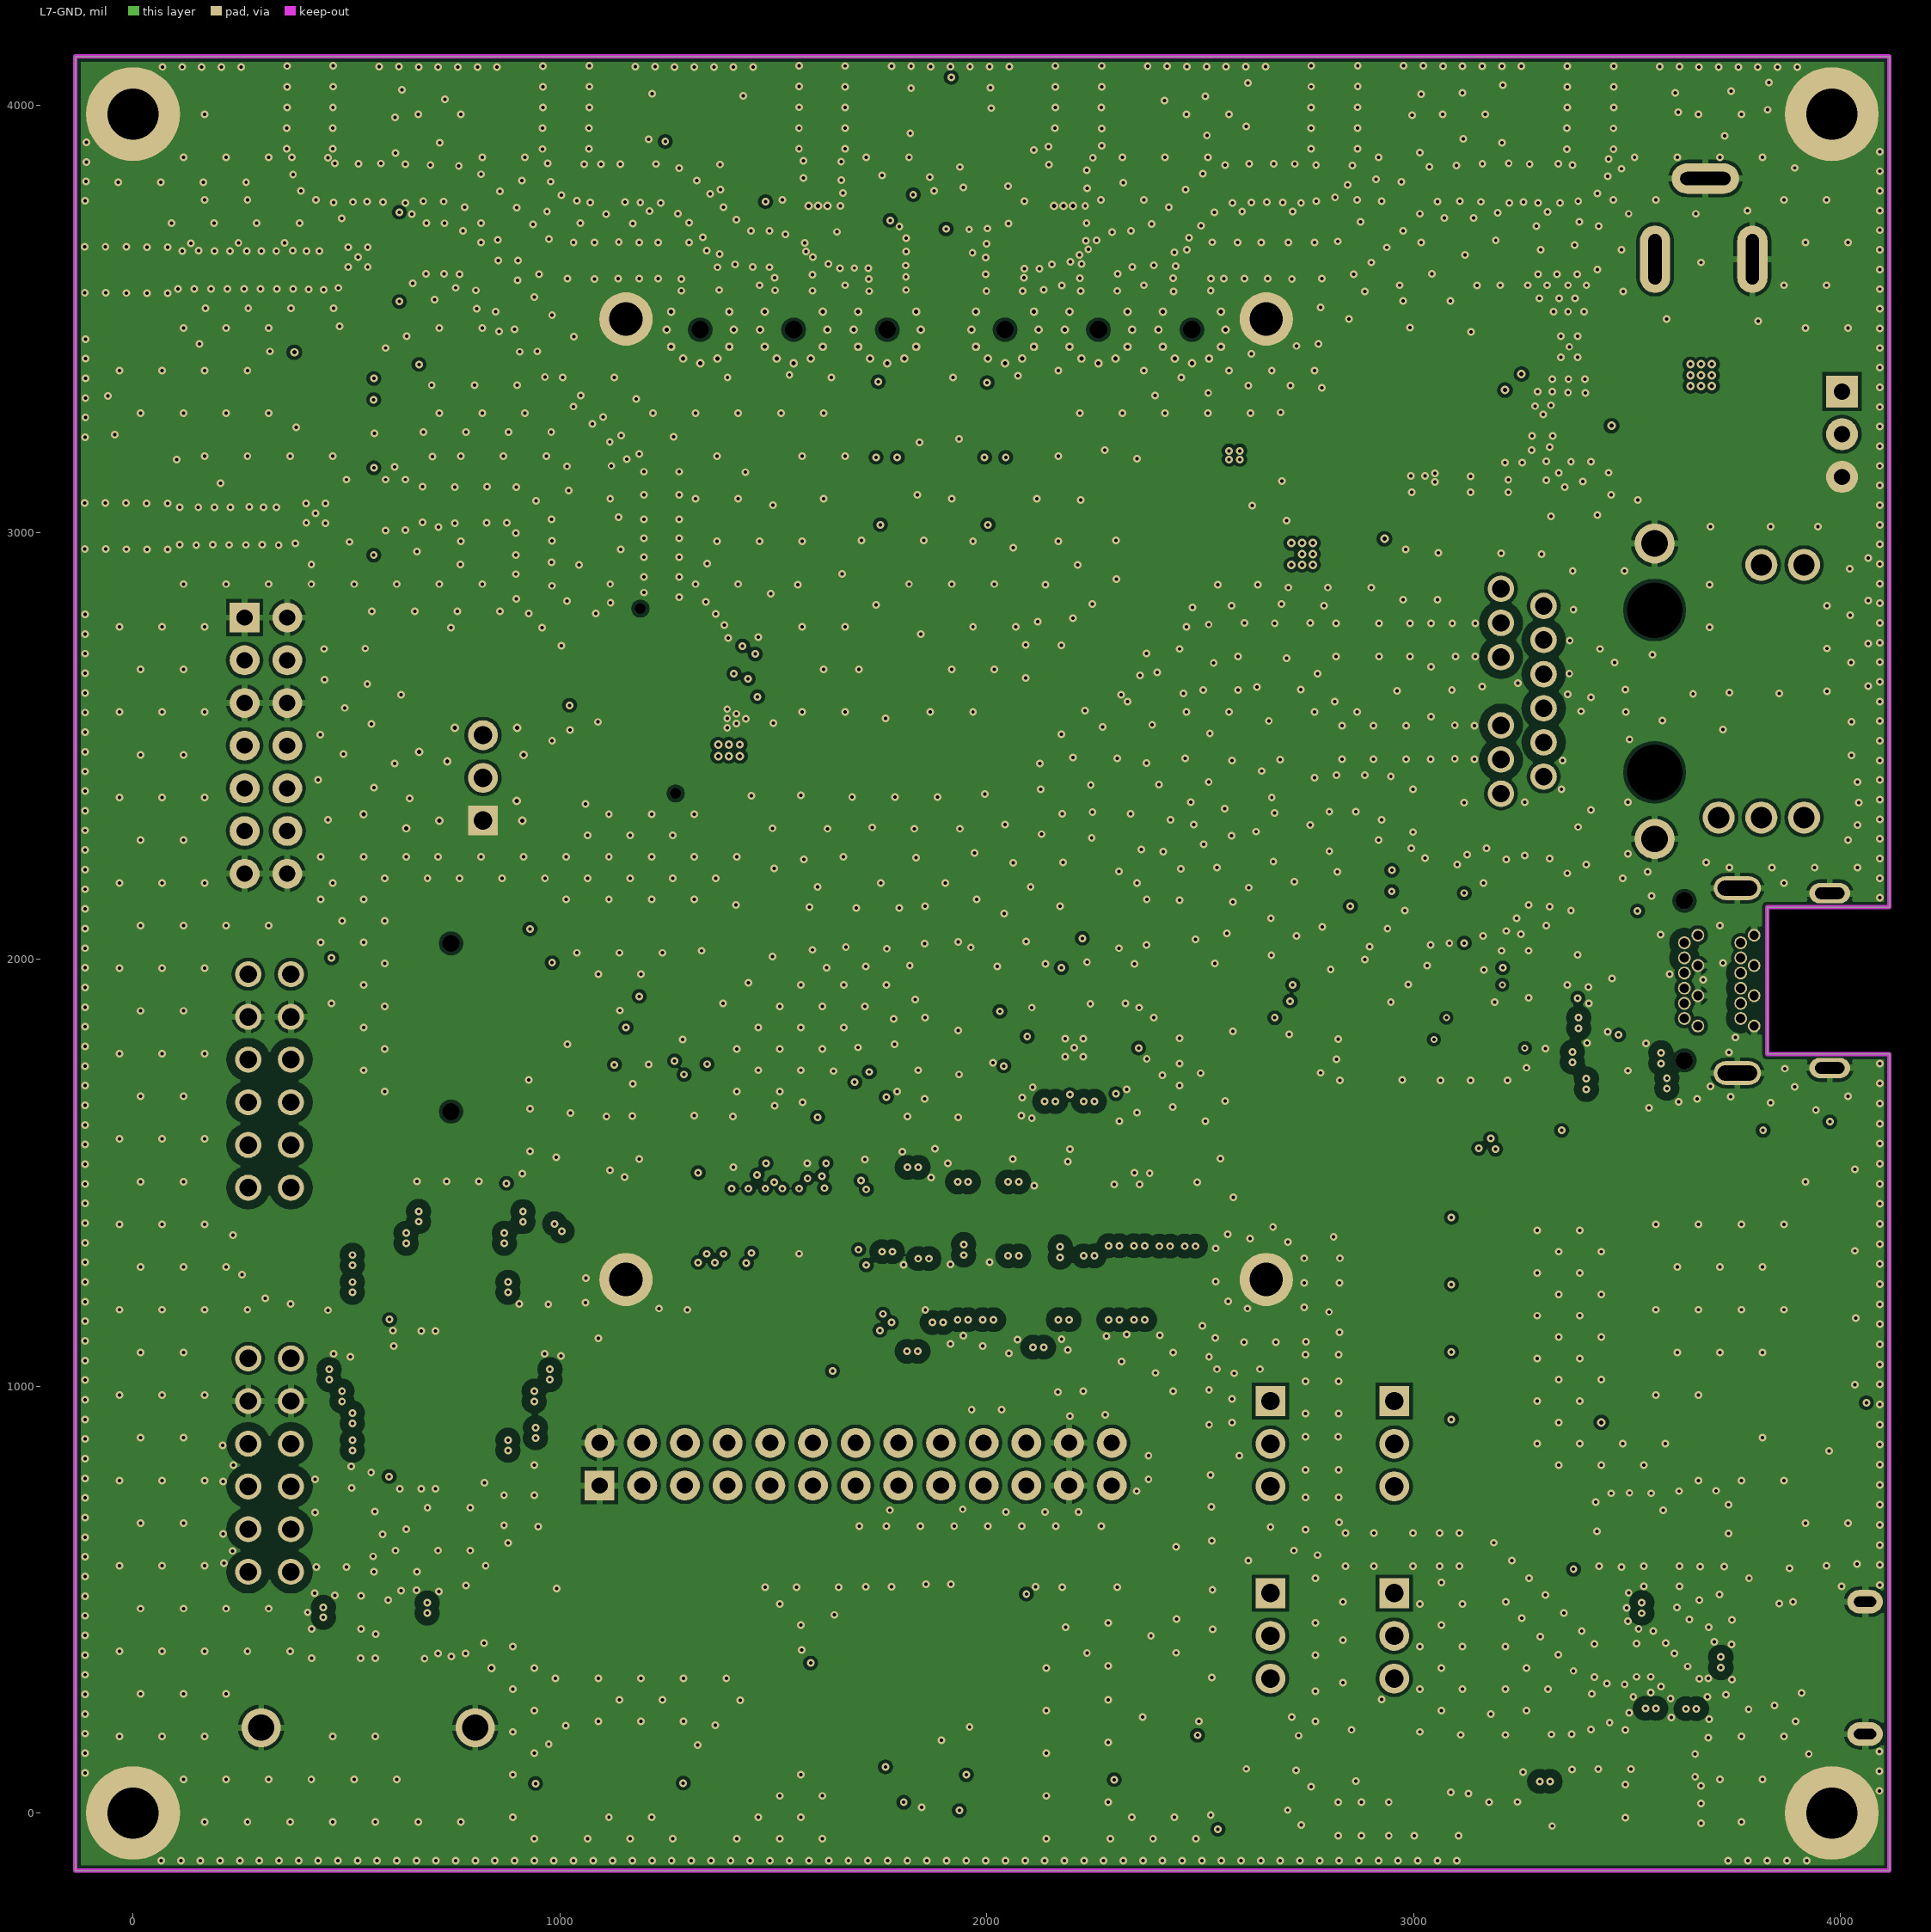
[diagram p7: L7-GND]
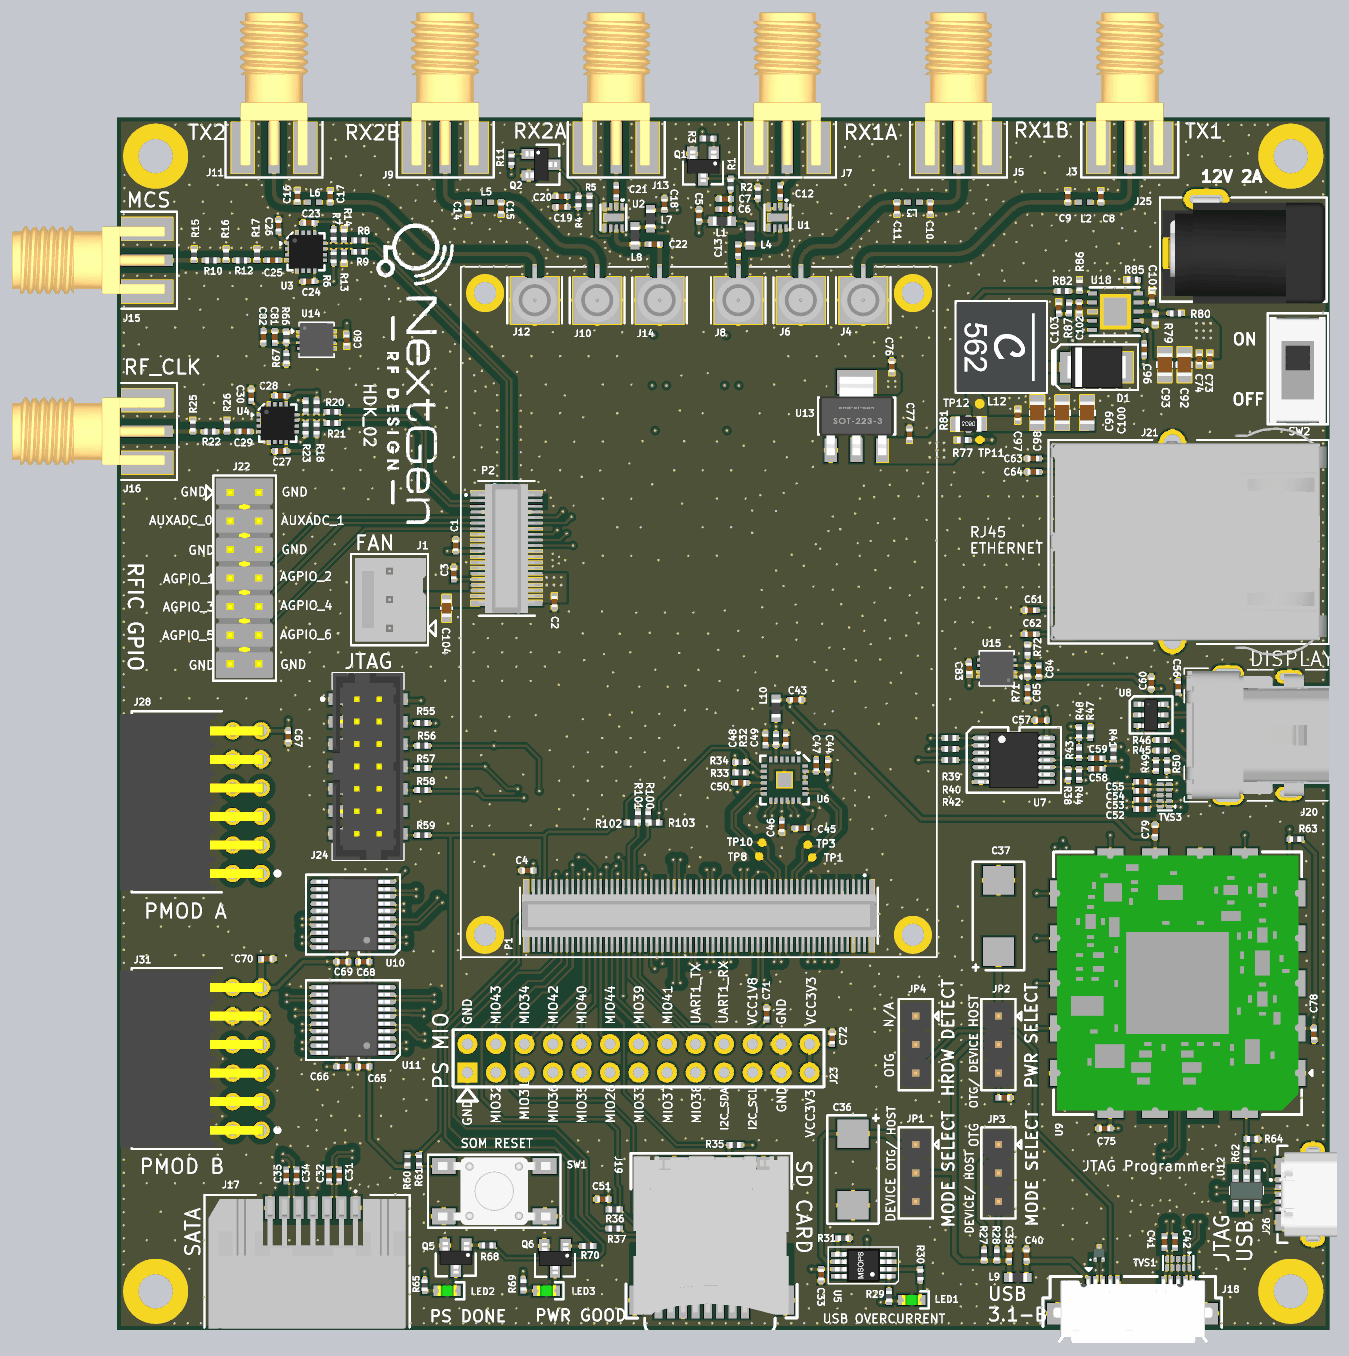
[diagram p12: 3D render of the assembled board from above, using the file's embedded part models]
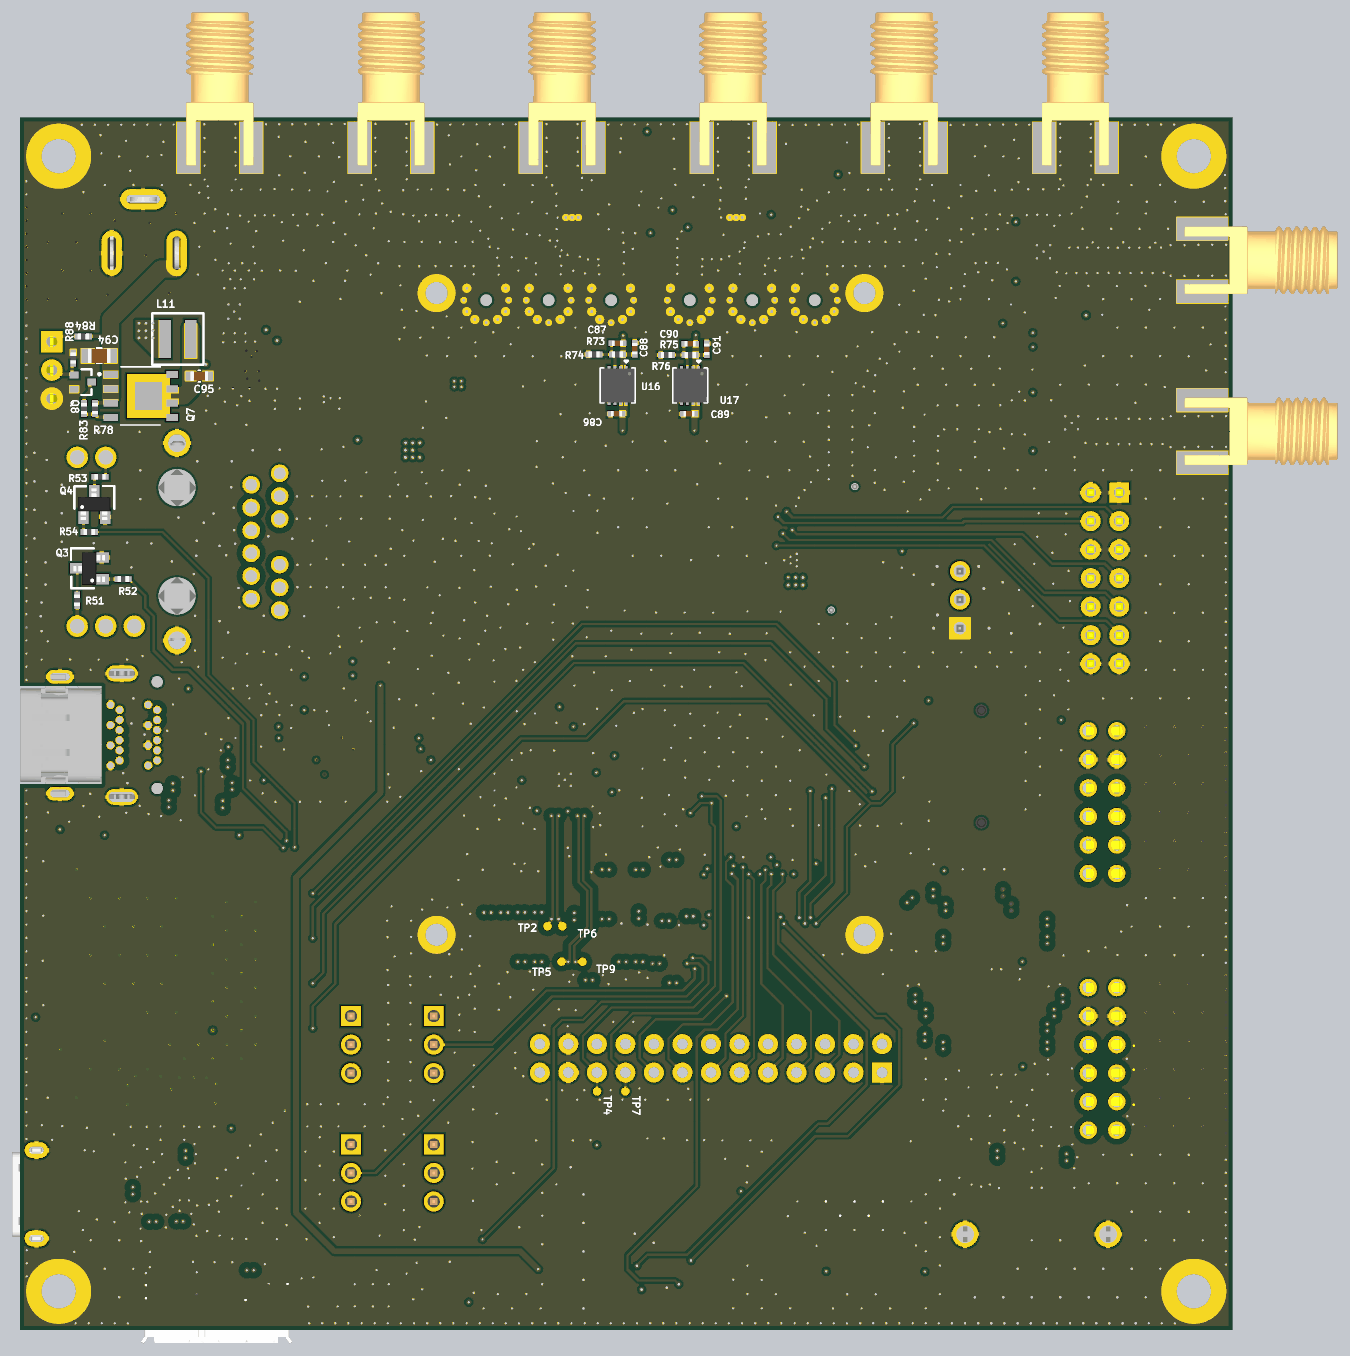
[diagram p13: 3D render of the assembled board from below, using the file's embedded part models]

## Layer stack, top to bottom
Top Solder: solder mask 0.4, Solder Resist, Dk 3.5
Top Layer: signal copper 1.4
Dielectric 1: core 8, 370HR, Dk 4
L2-GND: signal copper 0.7
Dielectric 2: prepreg 8, 370HR, Dk 4
L3-SIG: signal copper 0.7
Dielectric 3: core 8, 370HR, Dk 4
L4-GND: signal copper 0.7
Dielectric 4: prepreg 8, 370HR, Dk 4
L5-PWR: signal copper 0.7
Dielectric 5: core 8, 370HR, Dk 4
L6-SIG: signal copper 0.7
Dielectric 6: prepreg 8, 370HR, Dk 4
L7-GND: signal copper 0.7
Dielectric 7: core 8, 370HR, Dk 4
Bottom Layer: signal copper 1.4
Bottom Solder: solder mask 0.4, Solder Resist, Dk 3.5

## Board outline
-135,-135 -135,4115 4115,4115 4115,2122 3829,2122 3829,1778 4115,1778 4115,-135

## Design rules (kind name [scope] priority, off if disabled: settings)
Clearance "Clearance_95Ohm Diff" [InDifferentialPairClass('95OHM_DIFF') vs InPoly] p1: gap=20 ignorepadtopadclearanceinfootprint=FALSE
Clearance Clearance_50Ohm [InNetClass('50OHM_SE') vs InPoly] p2: gap=25 ignorepadtopadclearanceinfootprint=FALSE
Clearance Clearance_Board_Edge [(OnLayer('Keep-Out Layer')) vs InPoly] p3: gap=20 ignorepadtopadclearanceinfootprint=FALSE except(0: Arc-Hole Track-Hole SMDPad-Hole THPad-Hole Via-Hole Fill-Hole Poly-Hole Region-Hole Text-Hole)
Clearance Clearance_General_Polygon [All vs inPoly] p4: gap=8 ignorepadtopadclearanceinfootprint=TRUE
Clearance [All] p5: gap=6 ignorepadtopadclearanceinfootprint=TRUE
ComponentClearance [All] p1: gap=10 collisioncheckmode=3 verticalgap=-200 showdistances=FALSE
DiffPairsRouting DiffPairsRouting_95 [InDifferentialPairClass('95OHM_DIFF')] p1: maxlimit=6 minlimit=1 mostfreqgap=6 toplayer_mingap=6 toplayer_minwidth=8.75 toplayer_maxwidth=8.75 toplayer_prefwidth=8.75 midlayer2_mingap=6 midlayer2_minwidth=5.5 midlayer2_maxwidth=5.5 midlayer2_prefwidth=5.5 midlayer3_mingap=6 midlayer3_minwidth=5.5 midlayer3_maxwidth=5.5 midlayer3_prefwidth=5.5 midlayer4_mingap=6 midlayer4_minwidth=5.5 midlayer4_maxwidth=5.5 midlayer4_prefwidth=5.5 midlayer5_mingap=6 midlayer5_minwidth=5.5 midlayer5_maxwidth=5.5 midlayer5_prefwidth=5.5 midlayer7_maxgap=1 midlayer7_prefgap=1 midlayer7_minwidth=1 midlayer7_maxwidth=1 midlayer7_prefwidth=1 midlayer8_maxgap=1 midlayer8_prefgap=1 midlayer8_minwidth=1 midlayer8_maxwidth=1 midlayer8_prefwidth=1 bottomlayer_mingap=6 bottomlayer_minwidth=8.75 bottomlayer_maxwidth=8.75 bottomlayer_prefwidth=8.75 maxuncoupledlength=500
FabricationTestPointUsage TestPointUsage [All] p1: valid=0 allowmultiple=FALSE
FabricationTestpoint Testpoint [All] p1: side=3 testpointundercomponent=TRUE minsize=40 maxsize=100 preferedsize=60 minholesize=0 maxholesize=40 preferedholesize=32 testpointgrid=1 allowsidetop=TRUE allowsidebottom=TRUE usegrid=TRUE gridtolerance=0.01
HoleSize [All] p1: absolutevalues=TRUE maxlimit=221 minlimit=1 maxpercent=80.000 minpercent=20.000
Length "SD1_BUS Length" [InNetClass('SD1_BUS')] p1: maxlimit=2280 minlimit=1880
MatchedLengths MatchLengths_xSignals_DisplayPort [InxSignalClass('DisplayPort_xSig')] p1: tolerance=100 checknetsindiffpair=FALSE checkdiffpairvsdiffpair=TRUE checkxsignals=TRUE checkothers=TRUE
MatchedLengths MatchLengths_xSignals_PMODA [InxSignalClass('xSignals_PMODA')] p2: tolerance=50 checknetsindiffpair=FALSE checkdiffpairvsdiffpair=TRUE checkxsignals=TRUE checkothers=TRUE
MatchedLengths MatchLengths_xSignals_PMODB [InxSignalClass('xSignals_PMODB')] p3: tolerance=50 checknetsindiffpair=FALSE checkdiffpairvsdiffpair=TRUE checkxsignals=TRUE checkothers=TRUE
MatchedLengths MatchedLengths_95Ohms_Diff [InDifferentialPairClass('95OHM_DIFF')] p4: tolerance=5 checknetsindiffpair=TRUE checkdiffpairvsdiffpair=FALSE checkxsignals=FALSE checkothers=FALSE
MatchedLengths MatchedLengths_JTAG_BUS_CLASS [InNetClass('JTAG_BUS')] p5: tolerance=250 checknetsindiffpair=FALSE checkdiffpairvsdiffpair=TRUE checkxsignals=TRUE checkothers=TRUE
MatchedLengths MatchedLengths_ETH_BUS [InNetClass('ETH_BUS')] p6: tolerance=50 checknetsindiffpair=FALSE checkdiffpairvsdiffpair=TRUE checkxsignals=TRUE checkothers=TRUE
MatchedLengths MatchedLengths_USB3_BUS [InNetClass('USB3_BUS')] p7: tolerance=2.5 checknetsindiffpair=TRUE checkdiffpairvsdiffpair=FALSE checkxsignals=FALSE checkothers=FALSE
MatchedLengths MatchedLengths_SATA_BUS [InNetClass('SATA_BUS')] p8: tolerance=5 checknetsindiffpair=TRUE checkdiffpairvsdiffpair=FALSE checkxsignals=FALSE checkothers=FALSE
MinimumAnnularRing [All] p1: minimumring=2.9
MinimumSolderMaskSliver [All] p1: minsoldermaskwidth=0.09
PlaneConnect "Via_ Direct_Connect_to_Plane" [IsVia] p1: planeconnectstyle=Direct reliefexpansion=20 reliefentries=4 reliefconductorwidth=10 reliefairgap=10
PlaneConnect [All] p2: planeconnectstyle=Relief reliefexpansion=20 reliefentries=4 reliefconductorwidth=10 reliefairgap=10
PolygonConnect PolygonConnect_Thermal [InComponentClass('Thermal Relief')] p1: connectstyle=Relief reliefconductorwidth=15 reliefentries=4 polygonreliefangle="90 Angle" airgapwidth=8
PolygonConnect PolygonConnect_Via [IsVia] p2: connectstyle=Direct reliefconductorwidth=10 reliefentries=4 polygonreliefangle="90 Angle" airgapwidth=10
PolygonConnect [All] p3: connectstyle=Direct reliefconductorwidth=10 reliefentries=4 polygonreliefangle="90 Angle" airgapwidth=6
RoutingTopology RoutingTopology_DDRAddressAndControls [InNetClass('DDR_AddressAndControls')] p1: topology=Daisy_Simple
RoutingTopology [All] p2: topology=Shortest
RoutingVias [All] p1: holewidth=10 width=22 viastyle="Through Hole" minholewidth=6 minwidth=12 maxholewidth=28 maxwidth=50
SilkToSilkClearance [All] p1: silktosilkclearance=2
SilkToSolderMaskClearance SilkscreenOverComponentPads [IsPad] p1: minsilkscreentomaskgap=0.1 clearancetoexposedcopper=FALSE
SolderMaskExpansion [All] p1: expansion=2 istentingtop=FALSE
Width [All] p1: maxlimit=125 minlimit=4 preferedwidth=8
Width "Width 50Ohm Microstrip" [InNetClass('50OHM_SE')] p2: maxlimit=15.35 minlimit=1 preferedwidth=1 toplayer_minwidth=15.35 toplayer_prefwidth=15.35 midlayer2_maxwidth=1 midlayer3_maxwidth=1 midlayer4_maxwidth=1 midlayer5_maxwidth=1 midlayer7_maxwidth=1 midlayer8_maxwidth=1 bottomlayer_minwidth=15.35 bottomlayer_prefwidth=15.35 minimp=50.000000 maximp=50.000000 favimp=50.000000
Width "Width 75Ohms" [InNetClass('75_Ohm')] p3: maxlimit=7 minlimit=4 preferedwidth=6.5 toplayer_maxwidth=5 toplayer_prefwidth=4 midlayer2_minwidth=5 midlayer3_minwidth=5 midlayer4_minwidth=5 midlayer5_minwidth=5 midlayer7_minwidth=5 midlayer7_prefwidth=5.5 midlayer8_minwidth=5 midlayer8_prefwidth=5.5 bottomlayer_maxwidth=5 bottomlayer_prefwidth=4 minimp=50.000000 maximp=50.000000 favimp=50.000000
20 further rules are at their usual default settings.

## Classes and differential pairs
component class "Thermal Relief": C1 C2 C3 C4 C5 C6 C7 C12 C13 C18 C19 C20 C21 C22 C23 C24 C25 C26 C27 C28 C29 C30 C31 C32 C33 C34 C35 C36 C37 C38 C39 C40 C41 C42 C43 C44 C45 C46 C47 C48 C49 C50 C51 C52 C53 C54 C55 C56 C57 C58 C59 C60 C61 C62 C63 C64 C65 C66 C67 C68 C69 C70 C71 C72 C75 C76 C77 C78 C79 C80 C81 C82 C83 C84 C85 C86 C87 C88 C89 C90 C91 J17 J18 J19 J20 J21 J22 J23 J24 J25 J26 J28 J31 JP1 JP2 JP3 JP4 L1 L2 L3 L4 L5 L6 L7 L8 L9 L10 LED1 LED2 LED3 Q1 Q2 Q3 Q4 Q5 Q6 R1 R2 R3 R4 R5 R6 R7 R8 R9 R10 R11 R12 R18 R19 R20 R21 R22 R23 R24 R27 R28 R29 R30 R31 R32 R33 R34 R35 R36 R37 R38 R39 R40 R41 R42 R43 R44 R45 R46 R47 R48 R49 R50 R51 R52 R53 R54 R55 R56 R57 R58 R59 R60 R61 R62 R63 R64 R65 R66 R67 R68 R69 R70 R71 R72 R73 R74 R75 R76 SW1 TVS1 TVS2 TVS3 U5 U6 U7 U8 U9 U10 U11 U12 U13 U14 U15 U16 U17
differential pair class 95OHM_DIFF: DP_TX2 DP_TX3 DPAUX_C ETH_MD1 ETH_MD2 ETH_MD3 ETH_MD4 GTR_REFCLK0 GTR_REFCLK1 GTR_REFCLK2 GTR_REFCLK3 GTR_RX0 GTR_RX1 GTR_TX0 GTR_TX1 GTR_TX2 GTR_TX3 IO_L1 IO_L2 IO_L3 IO_L4 IO_L5 IO_L10 IO_L11 IO_L12 MCS MCS0 PMOD_A0 PMOD_A1 PMOD_A2 PMOD_A3 PMOD_B0 PMOD_B1 PMOD_B2 PMOD_B3 RF_CLK RF_CLK0 SATA_RX SATA_TX USB USB3_TX0 USB_JTAG
net class USB_JTAG_BUS: USB_JTAG_N USB_JTAG_P
net class USB3_BUS: GTR_RX0_N GTR_RX0_P GTR_TX0_N GTR_TX0_P USB3_TX0_N USB3_TX0_P
net class USB2_BUS: USB_N USB_P
net class SD1_BUS: MIO46 MIO47 MIO48 MIO49 MIO50 MIO51 NetJ19_5
net class SATA_BUS: GTR_RX1_N GTR_RX1_P GTR_TX1_N GTR_TX1_P SATA_RX_N SATA_RX_P SATA_TX_N SATA_TX_P
net class RF_CLK_BUS: RF_CLK0_N RF_CLK0_P RF_CLK_N RF_CLK_P
net class PMODB_BUS: IO_L5_N IO_L5_P IO_L10_N IO_L10_P IO_L11_N IO_L11_P IO_L12_N IO_L12_P PMOD_B0_N PMOD_B0_P PMOD_B1_N PMOD_B1_P PMOD_B2_N PMOD_B2_P PMOD_B3_N PMOD_B3_P
net class PMODA_BUS: IO_L1_N IO_L1_P IO_L2_N IO_L2_P IO_L3_N IO_L3_P IO_L4_N IO_L4_P PMOD_A0_N PMOD_A0_P PMOD_A1_N PMOD_A1_P PMOD_A2_N PMOD_A2_P PMOD_A3_N PMOD_A3_P
net class MCS_BUS: MCS0_N MCS0_P MCS_N MCS_P
net class JTAG_BUS: PS_JTAG_TCK PS_JTAG_TDI PS_JTAG_TDO PS_JTAG_TMS PS_SRST_N
net class GTR_CLK: GTR_REFCLK0_N GTR_REFCLK0_P GTR_REFCLK1_N GTR_REFCLK1_P GTR_REFCLK2_N GTR_REFCLK2_P GTR_REFCLK3_N GTR_REFCLK3_P
net class ETH_BUS: ETH_MD1_N ETH_MD1_P ETH_MD2_N ETH_MD2_P ETH_MD3_N ETH_MD3_P ETH_MD4_N ETH_MD4_P
net class DP_GTR_BUS: DP_TX2_N DP_TX2_P DP_TX3_N DP_TX3_P GTR_TX2_N GTR_TX2_P GTR_TX3_N GTR_TX3_P
net class DP_AUX_BUS: DPAUX_C_N DPAUX_C_P
net class 50OHM_SE: NetC8_1 NetC9_1 NetC10_1 NetC11_1 NetC12_1 NetC12_2 NetC13_1 NetC13_2 NetC14_1 NetC15_1 NetC16_1 NetC17_1 NetC21_1 NetC21_2 NetC22_1 NetC22_2 NetC25_1 NetC25_2 NetC29_1 NetC29_2 NetJ15_1 NetJ16_1 NetR10_1
component class "7-JTAG & Power": C73 C74 C75 C76 C77 C78 C79 C80 C81 C82 C83 C84 C85 C86 C87 C88 C89 C90 C91 C92 C93 C94 C95 C96 C97 C98 C99 C100 C101 C102 C103 C104 D1 J1 J24 J25 J26 L11 L12 LED2 LED3 Q5 Q6 Q7 Q8 R55 R56 R57 R58 R59 R60 R61 R62 R63 R64 R65 R66 R67 R68 R69 R70 R71 R72 R73 R74 R75 R76 R77 R78 R79 R80 R81 R82 R83 R84 R85 R86 R87 R88 SW1 SW2 TP11 TP12 U9 U12 U13 U14 U15 U16 U17 U18
component class "6-User IO": C65 C66 C67 C68 C69 C70 C71 C72 J22 J23 J28 J31 U10 U11
component class "5-DisplayPort & Ethernet": C51 C52 C53 C54 C55 C56 C57 C58 C59 C60 C61 C62 C63 C64 J19 J20 J21 Q3 Q4 R35 R36 R37 R38 R39 R40 R41 R42 R43 R44 R45 R46 R47 R48 R49 R50 R51 R52 R53 R54 TVS3 U7 U8
component class "4-USB & SATA": C31 C32 C33 C34 C35 C36 C37 C38 C39 C40 C41 C42 C43 C44 C45 C46 C47 C48 C49 C50 J17 J18 JP1 JP2 JP3 JP4 L9 L10 LED1 R27 R28 R29 R30 R31 R32 R33 R34 S1 S2 S3 TP1 TP2 TP3 TP4 TP5 TP6 TP7 TP8 TP9 TP10 TVS1 TVS2 U5 U6
component class "3-RF Frontend": C5 C6 C7 C8 C9 C10 C11 C12 C13 C14 C15 C16 C17 C18 C19 C20 C21 C22 C23 C24 C25 C26 C27 C28 C29 C30 J3 J4 J5 J6 J7 J8 J9 J10 J11 J12 J13 J14 J15 J16 L1 L2 L3 L4 L5 L6 L7 L8 Q1 Q2 R1 R2 R3 R4 R5 R6 R7 R8 R9 R10 R11 R12 R13 R14 R15 R16 R17 R18 R19 R20 R21 R22 R23 R24 R25 R26 U1 U2 U3 U4
component class "2-SOM Interface": C1 C2 C3 C4 MH1 MH2 MH3 MH4 MH5 MH6 MH7 MH8 P1 P2 R100 R101 R102 R103
differential pair GTR_REFCLK2: +GTR_REFCLK2_P -GTR_REFCLK2_N
differential pair USB: +USB_P -USB_N
differential pair USB_JTAG: +USB_JTAG_P -USB_JTAG_N
differential pair USB3_TX0: +USB3_TX0_P -USB3_TX0_N
differential pair SATA_TX: +SATA_TX_P -SATA_TX_N
differential pair SATA_RX: +SATA_RX_P -SATA_RX_N
differential pair RF_CLK: +RF_CLK_P -RF_CLK_N
differential pair RF_CLK0: +RF_CLK0_P -RF_CLK0_N
differential pair PMOD_B3: +PMOD_B3_P -PMOD_B3_N
differential pair PMOD_B2: +PMOD_B2_P -PMOD_B2_N
differential pair PMOD_B1: +PMOD_B1_P -PMOD_B1_N
differential pair PMOD_B0: +PMOD_B0_P -PMOD_B0_N
differential pair PMOD_A3: +PMOD_A3_P -PMOD_A3_N
differential pair PMOD_A2: +PMOD_A2_P -PMOD_A2_N
differential pair PMOD_A1: +PMOD_A1_P -PMOD_A1_N
differential pair PMOD_A0: +PMOD_A0_P -PMOD_A0_N
differential pair MCS: +MCS_P -MCS_N
differential pair MCS0: +MCS0_P -MCS0_N
differential pair IO_L12: +IO_L12_P -IO_L12_N
differential pair IO_L11: +IO_L11_P -IO_L11_N
differential pair IO_L10: +IO_L10_P -IO_L10_N
differential pair IO_L5: +IO_L5_P -IO_L5_N
differential pair IO_L4: +IO_L4_P -IO_L4_N
differential pair IO_L3: +IO_L3_P -IO_L3_N
differential pair IO_L2: +IO_L2_P -IO_L2_N
differential pair IO_L1: +IO_L1_P -IO_L1_N
differential pair GTR_TX3: +GTR_TX3_P -GTR_TX3_N
differential pair GTR_TX2: +GTR_TX2_P -GTR_TX2_N
differential pair GTR_TX1: +GTR_TX1_P -GTR_TX1_N
differential pair GTR_TX0: +GTR_TX0_P -GTR_TX0_N
differential pair GTR_RX1: +GTR_RX1_P -GTR_RX1_N
differential pair GTR_RX0: +GTR_RX0_P -GTR_RX0_N
differential pair GTR_REFCLK3: +GTR_REFCLK3_P -GTR_REFCLK3_N
differential pair GTR_REFCLK1: +GTR_REFCLK1_P -GTR_REFCLK1_N
differential pair GTR_REFCLK0: +GTR_REFCLK0_P -GTR_REFCLK0_N
differential pair ETH_MD4: +ETH_MD4_P -ETH_MD4_N
differential pair ETH_MD3: +ETH_MD3_P -ETH_MD3_N
differential pair ETH_MD2: +ETH_MD2_P -ETH_MD2_N
differential pair ETH_MD1: +ETH_MD1_P -ETH_MD1_N
differential pair DPAUX_C: +DPAUX_C_P -DPAUX_C_N
differential pair DP_TX3: +DP_TX3_P -DP_TX3_N
differential pair DP_TX2: +DP_TX2_P -DP_TX2_N

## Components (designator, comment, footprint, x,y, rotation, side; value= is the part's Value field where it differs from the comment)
C1 "CAP_CERAMIC_0402" SM/0402/CAP 1052,2615 r90 top locked value=4.7uF
C2 "CAP_CERAMIC_0402" SM/0402/CAP 1398,2418 r270 top locked value=10uF
C3 "CAP_CERAMIC_0402" SM/0402/CAP 1045,2517 r90 top locked value=10uF
C4 "CAP_CERAMIC_0402" SM/0402/CAP 1304.3,1475.39 r180 top locked value=4.7uF
C5 "CAP_CERAMIC_0402" SM/0402/CAP 1905,3772 r90 top locked value=10uF
C6 "CAP_CERAMIC_0402" SM/0402/CAP 1996,3794 r180 top locked value=100pF
C7 "CAP_CERAMIC_0402" SM/0402/CAP 1996,3830 r180 top locked value=1uF
C8 "CAP_CERAMIC_0402" SM/0402/CAP 3314,3838 r90 top locked value=DNP
C9 "CAP_CERAMIC_0402" SM/0402/CAP 3198,3838 r90 top locked value=DNP
C10 "CAP_CERAMIC_0402" SM/0402/CAP 2716,3798 r270 top locked value=DNP
C11 "CAP_CERAMIC_0402" SM/0402/CAP 2599,3798 r270 top locked value=DNP
C12 "CAP_CERAMIC_0402" SM/0402/CAP 2190,3857 r270 top locked value=100pF
C13 "CAP_CERAMIC_0402" SM/0402/CAP 2042,3650 r270 top value=100pF
C14 "CAP_CERAMIC_0402" SM/0402/CAP 1095,3798 r270 top locked value=DNP
C15 "CAP_CERAMIC_0402" SM/0402/CAP 1211,3798 r270 top locked value=DNP
C16 "CAP_CERAMIC_0402" SM/0402/CAP 497,3839 r90 top locked value=DNP
C17 "CAP_CERAMIC_0402" SM/0402/CAP 612,3838 r90 top locked value=DNP
C18 "CAP_CERAMIC_0402" SM/0402/CAP 1784,3811 r90 top locked value=10uF
C19 "CAP_CERAMIC_0402" SM/0402/CAP 1423,3802 r180 top locked value=100pF
C20 "CAP_CERAMIC_0402" SM/0402/CAP 1423,3839 r180 top locked value=1uF
C21 "CAP_CERAMIC_0402" SM/0402/CAP 1615,3856 r270 top locked value=100pF
C22 "CAP_CERAMIC_0402" SM/0402/CAP 1748,3671 r0 top locked value=100pF
C23 "CAP_CERAMIC_0402" SM/0402/CAP 537,3746 r180 top locked value=4.7uF
C24 "CAP_CERAMIC_0402" SM/0402/CAP 537,3541 r180 top locked value=0.1uF
C25 "CAP_CERAMIC_0402" SM/0402/CAP 410,3615 r0 top locked value=10000pF
C26 "CAP_CERAMIC_0402" SM/0402/CAP 430.55,3735.87 r90 top locked value=0.1uF
C27 "CAP_CERAMIC_0402" SM/0402/CAP 438,2946 r180 top locked value=4.7uF
C28 "CAP_CERAMIC_0402" SM/0402/CAP 438,3140 r180 top locked value=0.1uF
C29 "CAP_CERAMIC_0402" SM/0402/CAP 310,3015 r0 top locked value=10000pF
C30 "CAP_CERAMIC_0402" SM/0402/CAP 335,3142 r90 top locked value=0.1uF
C31 "CAP_CERAMIC_0402" SM/0402/CAP 644,406 r270 top locked value=0.1uF
C32 "CAP_CERAMIC_0402" SM/0402/CAP 608,406 r270 top locked value=0.1uF
C33 "CAP_CERAMIC_0402" SM/0402/CAP 2333,58 r270 top locked value=0.1uF
C34 "CAP_CERAMIC_0402" SM/0402/CAP 494,406 r270 top locked value=0.1uF
C35 "CAP_CERAMIC_0402" SM/0402/CAP 458,406 r270 top locked value=0.1uF
C36 "TANT-D" SM/CAP/TANT-D_A 2445,427 r270 top locked value=150uF
C37 "TANT-D" SM/CAP/TANT-D_A 2955,1316 r90 top locked value=150uF
C38 "CAP_CERAMIC_0402" SM/0402/CAP 2975,679 r0 top locked value=4.7uF
C39 "CAP_CERAMIC_0402" SM/0402/CAP 2993,127 r90 top locked value=4.7uF
C40 "CAP_CERAMIC_0402" SM/0402/CAP 3053,127 r90 top locked value=0.1uF
C41 "CAP_CERAMIC_0402" SM/0402/CAP 3537,173 r270 top locked value=0.1uF
C42 "CAP_CERAMIC_0402" SM/0402/CAP 3574,173 r270 top locked value=0.1uF
C43 "CAP_CERAMIC_0402" SM/0402/CAP 2244,2074 r0 top locked value=4.7uF
C44 "CAP_CERAMIC_0402" SM/0402/CAP 2356,1843 r90 top locked value=0.1uF
C45 "CAP_CERAMIC_0402" SM/0402/CAP 2262.92,1623.47 r180 top locked value=0.1uF
C46 "CAP_CERAMIC_0402" SM/0402/CAP 2195,1630 r270 top locked value=0.1uF
C47 "CAP_CERAMIC_0402" SM/0402/CAP 2316,1843 r90 top locked value=4.7uF
C48 "CAP_CERAMIC_0402" SM/0402/CAP 2138,1935 r90 top locked value=4.7uF
C49 "CAP_CERAMIC_0402" SM/0402/CAP 2209,1935 r90 top locked value=0.1uF
C50 "CAP_CERAMIC_0402" SM/0402/CAP 2051,1783 r180 top locked value=0.1uF
C51 "CAP_CERAMIC_0402" SM/0402/CAP 1568,323 r180 top locked value=0.1uF
C52 "CAP_CERAMIC_0402" SM/0402/CAP 3457,1691 r0 top locked value=0.1uF
C53 "CAP_CERAMIC_0402" SM/0402/CAP 3457,1723.33 r0 top locked value=0.1uF
C54 "CAP_CERAMIC_0402" SM/0402/CAP 3457,1754.67 r0 top locked value=0.1uF
C55 "CAP_CERAMIC_0402" SM/0402/CAP 3457,1787 r0 top locked value=0.1uF
C56 "CAP_CERAMIC_0402" SM/0402/CAP 3585,2120 r90 top locked value=0.1uF
C57 "CAP_CERAMIC_0402" SM/0402/CAP 3104,2002 r180 top locked value=0.1uF
C58 "CAP_CERAMIC_0402" SM/0402/CAP 3300,1832 r0 top locked value=0.1uF
C59 "CAP_CERAMIC_0402" SM/0402/CAP 3300,1869 r0 top locked value=0.1uF
C60 "CAP_CERAMIC_0402" SM/0402/CAP 3491,2133 r90 top locked value=0.1uF
C61 "CAP_CERAMIC_0402" SM/0402/CAP 3067,2388 r0 top value=0.1uF
C62 "CAP_CERAMIC_0402" SM/0402/CAP 3067,2304 r0 top value=0.1uF
C63 "CAP_CERAMIC_0402" SM/0402/CAP 3077,2920 r0 top value=0.1uF
C64 "CAP_CERAMIC_0402" SM/0402/CAP 3077,2873 r0 top value=0.1uF
C65 "CAP_CERAMIC_0402" SM/0402/CAP 729,788 r180 top locked value=0.1uF
C66 "CAP_CERAMIC_0402" SM/0402/CAP 655,788 r180 top locked value=0.1uF
C67 "CAP_CERAMIC_0402" SM/0402/CAP 465,1945 r270 top locked value=4.7uF
C68 "CAP_CERAMIC_0402" SM/0402/CAP 729,1156 r180 top locked value=0.1uF
C69 "CAP_CERAMIC_0402" SM/0402/CAP 655,1156 r180 top locked value=0.1uF
C70 "CAP_CERAMIC_0402" SM/0402/CAP 389.76,1165.63 r0 top locked value=4.7uF
C71 "CAP_CERAMIC_0402" SM/0402/CAP 2142,973 r90 top locked value=4.7uF
C72 "CAP_CERAMIC_0402" SM/0402/CAP 2372,887 r90 top locked value=4.7uF
C73 "" SM/0402/CAP 3696,3269 r90 top value=1000pF
C74 "" SM/0402/CAP 3659,3269 r90 top value=1000pF
C75 "CAP_CERAMIC_0402" SM/0402/CAP 3327.18,571.03 r180 top locked value=4.7uF
C76 "CAP_CERAMIC_0402" SM/0402/CAP 2581,3242 r90 top value=4.7uF
C77 "CAP_CERAMIC_0402" SM/0402/CAP 2643,3005 r90 top value=10uF
C78 "CAP_CERAMIC_0402" SM/0402/CAP 4061,902 r270 top locked value=0.1uF
C79 "CAP_CERAMIC_0402" SM/0402/CAP 3504,1614 r90 top locked value=0.1uF
C80 "CAP_CERAMIC_0402" SM/0402/CAP 670,3335 r270 top locked value=10uF
C81 "CAP_CERAMIC_0402" SM/0402/CAP 418,3346 r270 top locked value=0.1uF
C82 "CAP_CERAMIC_0402" SM/0402/CAP 378,3346 r270 top locked value=4.7uF
C83 "CAP_CERAMIC_0402" SM/0402/CAP 2852,2184 r90 top locked value=10uF
C84 "CAP_CERAMIC_0402" SM/0402/CAP 3096,2174 r90 top locked value=0.1uF
C85 "CAP_CERAMIC_0402" SM/0402/CAP 3057,2095 r270 top locked value=4.7uF
C86 "CAP_CERAMIC_0402" SM/0402/CAP 2024,3077 r0 bottom locked value=10uF
C87 "CAP_CERAMIC_0402" SM/0402/CAP 2021,3324 r0 bottom locked value=0.1uF
C88 "CAP_CERAMIC_0402" SM/0402/CAP 1960,3305 r90 bottom locked value=4.7uF
C89 "CAP_CERAMIC_0402" SM/0402/CAP 1770,3077 r0 bottom locked value=10uF
C90 "CAP_CERAMIC_0402" SM/0402/CAP 1766,3322 r0 bottom locked value=0.1uF
C91 "CAP_CERAMIC_0402" SM/0402/CAP 1708,3303 r90 bottom locked value=4.7uF
C92 "CAP_CERAMIC_0805" SM/0805/CAP 3607,3249 r270 top value=10uF
C93 "CAP_CERAMIC_0805" SM/0805/CAP 3538,3249 r270 top value=10uF
C94 "CAP_CERAMIC_0805" SM/0805/CAP 3838,3280 r0 bottom value=10uF
C95 "CAP_CERAMIC_0603" SM/0603/CAP 3487,3209 r180 bottom value=1uF
C96 "CAP_CERAMIC_0402" SM/0402/CAP 3466,3302 r270 top value=0.1uF
C97 "" SM/0402/CAP 3023,3072 r270 top value=1000pF
C98 "CAP_CERAMIC_0805" SM/0805/CAP 3091,3080 r90 top value=22uF
C99 "CAP_CERAMIC_0805" SM/0805/CAP 3178.5,3080 r90 top value=22uF
C100 "CAP_CERAMIC_0805" SM/0805/CAP 3266,3080 r90 top value=22uF
C101 "" SM/0402/CAP 3493,3487 r270 top value=0.01uF
C102 "" SM/0402/CAP 3238,3448 r90 top value=47pF
C103 "" SM/0402/CAP 3166,3448 r90 top value=4700pF
C104 "CAP_CERAMIC_0603" SM/0603/CAP 1019.97,2394.97 r270 top value=1uF
D1 "DIODE_SCHOTTKY SMB" SM/DO-214AA/SMB_A 3299,3240 r0 top value=STPS5L60U
J1 "0022112032" CON/MLX/0022112032/3P 820,2325 r90 top
J3 "CON_RF_SMA_BRD-EDGE_C" SM/CON/RF/SMA/BRD-EDGE_C 3415,4115 r0 top locked value="TX1 SMA"
J4 "CON_RF_SMPM_SMT_AMPHENOL" SM/CON/RF/SMPM/VERT_A 2481,3475 r180 top value="TX1 SMPM"
J5 "CON_RF_SMA_BRD-EDGE_C" SM/CON/RF/SMA/BRD-EDGE_C 2815,4115 r0 top locked value="RX1B SMA"
J6 "CON_RF_SMPM_SMT_AMPHENOL" SM/CON/RF/SMPM/VERT_A 2262,3475 r180 top value="RX1B SMPM"
J7 "CON_RF_SMA_BRD-EDGE_C" SM/CON/RF/SMA/BRD-EDGE_C 2215,4115 r0 top locked value="RX1A SMA"
J8 "CON_RF_SMPM_SMT_AMPHENOL" SM/CON/RF/SMPM/VERT_A 2043,3475 r180 top value="RX1A SMPM"
J9 "CON_RF_SMA_BRD-EDGE_C" SM/CON/RF/SMA/BRD-EDGE_C 1015,4115 r0 top locked value="RX2B SMA"
J10 "CON_RF_SMPM_SMT_AMPHENOL" SM/CON/RF/SMPM/VERT_A 1548,3475 r180 top value="RX2B SMPM"
J11 "CON_RF_SMA_BRD-EDGE_C" SM/CON/RF/SMA/BRD-EDGE_C 415,4115 r0 top locked value="TX2 SMA"
J12 "CON_RF_SMPM_SMT_AMPHENOL" SM/CON/RF/SMPM/VERT_A 1329,3475 r180 top value="TX2 SMPM"
J13 "CON_RF_SMA_BRD-EDGE_C" SM/CON/RF/SMA/BRD-EDGE_C 1615,4115 r0 top locked value="RX2A SMA"
J14 "CON_RF_SMPM_SMT_AMPHENOL" SM/CON/RF/SMPM/VERT_A 1767,3475 r180 top value="RX2A SMPM"
J15 "CON_RF_SMA_BRD-EDGE_C" SM/CON/RF/SMA/BRD-EDGE_C -135,3615 r90 top locked value="MCS SMA"
J16 "CON_RF_SMA_BRD-EDGE_C" SM/CON/RF/SMA/BRD-EDGE_C -135,3015 r90 top locked value="RF CLK SMA"
J17 "CON_MOLEX_0470804002" SM/CON/MLX/SATA/0470804002 701,293 r0 top locked value=0470804002
J18 "CON_USB_3.1_MICRO-B_RA" "SM/CON/USB3.1/MICRO B" 3270,27 r0 top locked value=GSB443133HR
J19 "CONN MICRO SD CARD HINGED TYPE" SM/CON/MICRO_SD-CARD/HOLDER 1944,195 r0 top value=DM3C-SF
J20 "CON_TE_2129320-3" CON/TE/2129320-3 3805,1950 r90 top locked value=2129320-3
J21 "CON_RJ45_MagJack_L829-1J1T-43" CON/RJ45/L829-1J1T-43 3305,2828 r270 top locked value="RJ45 10/100/1000"
J22 "CON_100SP_2X7P_VT" CON/100SP/2X7P/VT/038_A 311.5,2500.5 r270 top locked value=2x7
J23 "CON_100SP_2X13P_VERT" CON/100SP/2X13P/038_A 1093,767 r0 top locked value=2x13
J24 "CON_MOLEX_0878321420_14P" SM/CON/MLX/0878321420 745,1840 r270 top locked value=0878321420
J25 "CON_WURTH_694106301002" CON/WURTH/694106301002 3566,3640 r270 top value="2.1mm x 5.5mm"
J26 "CON_USB_MICRO-B_RA" "SM/CON/USB/MICRO B RA" 4058,340 r180 top locked value=1051640001
J28 "CON_100SP_2X6P_RA_PMOD" CON/SAMTEC/SSW/2X6/RA_A/PMOD 320,1715 r270 top locked value=PMODA
J31 "CON_100SP_2X6P_RA_PMOD" CON/SAMTEC/SSW/2X6/RA_A/PMOD 320,815 r270 top locked value=PMODB
JP1 "CON_100SP_1X3P_038H" CON/100SP/1X3P 2665,515 r270 top locked value=PH1-03-UA
JP2 "CON_100SP_1X3P_038H" CON/100SP/1X3P 2955,965 r270 top locked value=PH1-03-UA
JP3 "CON_100SP_1X3P_038H" CON/100SP/1X3P 2955,515 r270 top locked value=PH1-03-UA
JP4 "CON_100SP_1X3P_038H" CON/100SP/1X3P 2665,965 r270 top locked value=PH1-03-UA
L1 "FERRITE_0603_A" SM/0603 1986,3752 r0 top locked value="220Ohm @ 100MHz"
L2 "IND_0402" SM/0402 3256,3818 r180 top locked value=0
L3 "IND_0402" SM/0402 2657,3818 r180 top locked value=0
L4 "IND_0603" SM/0603 2084,3700 r90 top locked value=68nH
L5 "IND_0402" SM/0402 1153,3818 r0 top locked value=0
L6 "IND_0402" SM/0402 553,3818 r0 top locked value=0
L7 "FERRITE_0603_A" SM/0603 1735,3761 r270 top locked value="220Ohm @ 100MHz"
L8 "IND_0603" SM/0603 1680,3701 r90 top locked value=68nH
L9 "FERRITE_0603_A" SM/0603 3023,49 r0 top locked value="220Ohm @ 100MHz"
L10 "FERRITE_0603_A" SM/0603 2175,2044 r270 top locked value="220Ohm @ 100MHz"
L11 "IND_COILCRAFT_XAL4020" SM/IND/COILCRAFT/XAL4020 3562,3339 r0 bottom value=4.7uH
L12 "IND_COILCRAFT_XAL7030" SM/IND/COILCRAFT/XAL7030 2965,3311 r180 top value=5.6uH
LED1 "LED_0603" SM/LED_0603 2651,-30 r180 top locked value=RED
LED2 "LED_0603" SM/LED_0603 1022,2 r180 top locked value=GREEN
LED3 "LED_0603" SM/LED_0603 1370,2 r180 top locked value=GREEN
MH1 "HOLE_PTH_125/78" MTG125/78 1155,1250 r0 top locked
MH2 "HOLE_PTH_125/78" MTG125/78 2655,1250 r0 top locked
MH3 "HOLE_PTH_125/78" MTG125/78 1155,3500 r0 top locked
MH4 "HOLE_PTH_125/78" MTG125/78 2655,3500 r0 top locked
MH5 "HOLE_PTH_220/120" MTG220/120#1 0,1000 r0 top locked
MH6 "HOLE_PTH_220/120" MTG220/120#2 3980,0 r0 top locked
MH7 "HOLE_PTH_220/120" MTG220/120#2 0,3980 r0 top locked
MH8 "HOLE_PTH_220/120" MTG220/120#3 3880,3980 r0 top locked
P1 "WR-120S-VFH30-N1‎" SM/CON/JAE/WR-120S-VFH30-N1 1905,1317 r180 top locked value=WR-120S-VFH30-N1
P2 "WR-40SB-VFH30-N1‎" SM/CON/JAE/WR-40SB-VFH30-N1 1230,2605 r270 top locked value=WR-40SB-VFH30-N1
Q1 "TRANSISTOR_NPN_SOT23" SM/SOT23_A 1918.86,3945.17 r180 top locked value=MMBT3904
Q2 "TRANSISTOR_NPN_SOT23" SM/SOT23_A 1351,3950 r270 top locked value=MMBT3904
Q3 "TRANSISTOR_NPN_SOT23" SM/SOT23_A 3872,2535 r90 bottom value=MMBT3904
Q4 "TRANSISTOR_NPN_SOT23" SM/SOT23_A 3855,2759 r180 bottom value=MMBT3904
Q5 "TRANSISTOR_NPN_SOT23" SM/SOT23_A 1052,118 r180 top locked value=MMBT3904
Q6 "TRANSISTOR_NPN_SOT23" SM/SOT23_A 1400,116 r180 top locked value=MMBT3904
Q7 "MOSFET P-CH 20V 60A PPAK SO-8" SM/POWERPAK/VISHAY/SO-8 3745,3139 r270 bottom value=P-CH
Q8 "FET_N-CHANNEL_SC70" SM/SOT323_A 3895,3188 r270 bottom value=BSS138W
R1 "RES_0402_A" SM/0402/RES 2016,3882 r90 top locked value=10K
R2 "RES_0402_A" SM/0402/RES 2111,3851 r270 top locked value=DNP
R3 "RES_0402_A" SM/0402/RES 1937,4042 r0 top locked value=10K
R4 "RES_0402_A" SM/0402/RES 1482,3822 r90 top locked value=10K
R5 "RES_0402_A" SM/0402/RES 1521,3822 r90 top locked value=DNP
R6 "RES_0402_A" SM/0402/RES 624,3625 r90 top locked value=127
R7 "RES_0402_A" SM/0402/RES 624.03,3704.97 r270 top locked value=127
R8 "RES_0402_A" SM/0402/RES 714,3685 r180 top locked value=39
R9 "RES_0402_A" SM/0402/RES 714,3645 r180 top locked value=39
R10 "RES_0402_A" SM/0402/RES 194,3615 r180 top locked value=0
R11 "RES_0402_A" SM/0402/RES 1247,3968 r90 top locked value=10K
R12 "RES_0402_A" SM/0402/RES 301,3615 r180 top locked value=39
R13 "RES_0402_A" SM/0402/RES 661,3625 r270 top locked value=49.9
R14 "RES_0402_A" SM/0402/RES 661,3705 r90 top locked value=49.9
R15 "RES_0402_A" SM/0402/RES 135,3635 r90 top locked value=49.9
R16 "RES_0402_A" SM/0402/RES 247,3635 r90 top locked value=150
R17 "RES_0402_A" SM/0402/RES 355,3635 r90 top locked value=150
R18 "RES_0402_A" SM/0402/RES 564,3024 r90 top locked value=127
R19 "RES_0402_A" SM/0402/RES 564,3104 r270 top locked value=127
R20 "RES_0402_A" SM/0402/RES 619,3084 r180 top locked value=39
R21 "RES_0402_A" SM/0402/RES 619,3044 r180 top locked value=39
R22 "RES_0402_A" SM/0402/RES 190,3014 r180 top locked value=39
R23 "RES_0402_A" SM/0402/RES 526,3024 r270 top locked value=49.9
R24 "RES_0402_A" SM/0402/RES 526,3104 r90 top locked value=49.9
R25 "RES_0402_A" SM/0402/RES 130,3034 r90 top locked value=150
R26 "RES_0402_A" SM/0402/RES 250,3034 r90 top locked value=150
R27 "RES_0402_A" SM/0402/RES 2905,127 r90 top locked value=1K
R28 "RES_0402_A" SM/0402/RES 2949,127 r270 top locked value=10K
R29 "RES_0402_A" SM/0402/RES 2571,-18 r90 top locked value=10K
R30 "RES_0402_A" SM/0402/RES 2681,58 r90 top locked value=240
R31 "RES_0402_A" SM/0402/RES 2411,186 r0 top locked value=240
R32 "RES_0402_A" SM/0402/RES 2175,1935 r270 top locked value=2
R33 "RES_0402_A" SM/0402/RES 2051,1819 r0 top locked value=10K
R34 "RES_0402_A" SM/0402/RES 2051,1855 r0 top locked value=10K
R35 "RES_0402_A" SM/0402/RES 2031,513 r180 top locked value=4.7K
R36 "RES_0402_A" SM/0402/RES 1608,287 r0 top locked value=4.7K
R37 "RES_0402_A" SM/0402/RES 1608,220 r180 top locked value=39
R38 "RES_0402_A" SM/0402/RES 3200,1812 r90 top locked value=100K
R39 "RES_0402_A" SM/0402/RES 2786,1940 r180 top locked value=0
R40 "RES_0402_A" SM/0402/RES 2786,1902 r180 top locked value=0
R41 "RES_0402_A" SM/0402/RES 3358,1885 r90 top locked value=100K
R42 "RES_0402_A" SM/0402/RES 2786,1863 r180 top locked value=0
R43 "RES_0402_A" SM/0402/RES 3237,1889 r90 top locked value=49.9
R44 "RES_0402_A" SM/0402/RES 3237,1812 r270 top locked value=49.9
R45 "RES_0402_A" SM/0402/RES 3527,1896 r180 top locked value=1M
R46 "RES_0402_A" SM/0402/RES 3527,1933 r180 top locked value=1M
R47 "RES_0402_A" SM/0402/RES 3277,1960 r270 top locked value=1.5K
R48 "RES_0402_A" SM/0402/RES 3237,1960 r270 top locked value=2.49K
R49 "RES_0402_A" SM/0402/RES 3507,1843 r90 top locked value=39
R50 "RES_0402_A" SM/0402/RES 3545,1843 r90 top locked value=100K
R51 "RES_0402_A" SM/0402/RES 3915,2423 r270 bottom value=240
R52 "RES_0402_A" SM/0402/RES 3754,2497 r180 bottom value=100K
R53 "RES_0402_A" SM/0402/RES 3835,2856 r180 bottom value=240
R54 "RES_0402_A" SM/0402/RES 3873,2662 r180 bottom value=100K
R55 "RES_0402_A" SM/0402/RES 935,1992 r180 top locked value=39
R56 "RES_0402_A" SM/0402/RES 935,1913 r180 top locked value=39
R57 "RES_0402_A" SM/0402/RES 935,1835 r180 top locked value=39
R58 "RES_0402_A" SM/0402/RES 935,1757 r180 top locked value=39
R59 "RES_0402_A" SM/0402/RES 935,1599 r180 top locked value=39
R60 "RES_0402_A" SM/0402/RES 883,459 r270 top locked value=100K
R61 "RES_0402_A" SM/0402/RES 923,459 r90 top locked value=39
R62 "RES_0402_A" SM/0402/RES 3824.5,477 r90 top locked value=4.7K
R63 "RES_0402_A" SM/0402/RES 3995.5,1585 r180 top value=10K
R64 "RES_0402_A" SM/0402/RES 3844.5,534 r0 top locked value=10K
R65 "RES_0402_A" SM/0402/RES 943,21 r270 top locked value=240
R66 "RES_0402_A" SM/0402/RES 458,3346 r90 top locked value=120K
R67 "RES_0402_A" SM/0402/RES 458,3271 r90 top locked value=78.7K
R68 "RES_0402_A" SM/0402/RES 1163,161 r0 top locked value=100K
R69 "RES_0402_A" SM/0402/RES 1289,22 r270 top locked value=240
R70 "RES_0402_A" SM/0402/RES 1515,159 r0 top locked value=100K
R71 "RES_0402_A" SM/0402/RES 3057,2174 r270 top locked value=140K
R72 "RES_0402_A" SM/0402/RES 3057,2249 r270 top locked value=78.7K
R73 "RES_0402_A" SM/0402/RES 2021,3285 r180 bottom locked value=200k
R74 "RES_0402_A" SM/0402/RES 2103,3285 r180 bottom locked value=64.9K
R75 "RES_0402_A" SM/0402/RES 1766,3283 r180 bottom locked value=200k
R76 "RES_0402_A" SM/0402/RES 1849,3283 r180 bottom locked value=64.9K
R77 "RES_0402_A" SM/0402/RES 2830,2985 r0 top value=10K
R78 "RES_0402_A" SM/0402/RES 3853,3095 r270 bottom value=10K
R79 "RES_0402_A" SM/0402/RES 3505,3409 r270 top value=10K
R80 "RES_0402_A" SM/0402/RES 3576,3429 r180 top value=DNP
R81 "RES_0805_A" SM/0805/RES 2850,3041 r180 top value=0
R82 "RES_0402_A" SM/0402/RES 3181,3507 r180 top value=52.3K
R83 "RES_0402_A" SM/0402/RES 3891,3095 r90 bottom value=1K
R84 "RES_0402_A" SM/0402/RES 3894,3348 r0 bottom value=2K
R85 "RES_0402_A" SM/0402/RES 3425,3547 r180 top value=100K
R86 "RES_0402_A" SM/0402/RES 3239,3527 r90 top value=10K
R87 "RES_0402_A" SM/0402/RES 3202,3448 r90 top value=16.9K
R88 "RES_0402_A" SM/0402/RES 3929,3272 r90 bottom value=10K
R100 "RES_0402_A" SM/0402/RES 1727,1663 r270 top value=0
R101 "RES_0402_A" SM/0402/RES 1691,1663 r270 top value=0
R102 "RES_0402_A" SM/0402/RES 1671,1643 r0 top value=DNP
R103 "RES_0402_A" SM/0402/RES 1747,1643 r0 top value=DNP
SW1 "SWITCH_E-SWITCH_TACTILE_SPST" SM/SWITCH/E-SWITCH/SPST 1364,439 r180 top locked value=TL3301NF160QG
SW2 "AS1D-2M-10-Z" SWITCH/NIDEC/SPDT/AS1D-2M-10-Z 4004,3330 r0 top value=SPDT
TP1 "TESTPOINT_030" SM/TESTPOINT/30MIL 2302,1521 r0 top
TP2 "TESTPOINT_030" SM/TESTPOINT/30MIL 2266,1280 r0 bottom
TP3 "TESTPOINT_030" SM/TESTPOINT/30MIL 2286.17,1566 r180 top
TP4 "TESTPOINT_030" SM/TESTPOINT/30MIL 2092.32,700.75 r180 bottom
TP5 "TESTPOINT_030" SM/TESTPOINT/30MIL 2217,1156 r0 bottom
TP6 "TESTPOINT_030" SM/TESTPOINT/30MIL 2214,1280 r0 bottom
TP7 "TESTPOINT_030" SM/TESTPOINT/30MIL 1992.97,700.78 r180 bottom
TP8 "TESTPOINT_030" SM/TESTPOINT/30MIL 2116,1525 r0 top
TP9 "TESTPOINT_030" SM/TESTPOINT/30MIL 2143.82,1155.44 r0 bottom
TP10 "TESTPOINT_030" SM/TESTPOINT/30MIL 2126.36,1573 r90 top
TP11 "TESTPOINT_030" SM/TESTPOINT/30MIL 2889.97,2985.03 r180 top
TP12 "TESTPOINT_030" SM/TESTPOINT/30MIL 2889,3112 r180 top
TVS1 "TVS_TPD4E05U06_2.5mmX1mm" SM/DFN10/2.5X1MM_A 3585,98 r180 top locked value=TPD4E05U06-Q1
TVS2 "TVS_TPD2EUSB30DRTR_SOT3" SM/SOT3_A 3294,111 r0 top locked value=TPD2EUSB30DRTR
TVS3 "TVS_TPD4E05U06_2.5mmX1mm" SM/DFN10/2.5X1MM_A 3537.58,1739 r90 top locked value=TPD4E05U06-Q1
U1 "IC_TQP3M9035_DFN-8" SM/DFN8/2X2MM_E 2180,3765 r180 top locked value=TQP3M9035
U2 "IC_TQP3M9035_DFN-8" SM/DFN8/2X2MM_E 1605,3765 r180 top locked value=TQP3M9035
U3 "IC_ADCLK944_QFN16" SM/QFN16/3X3/0.5LS_A 527,3645 r270 top locked value=ADCLK944
U4 "IC_ADCLK944_QFN16" SM/QFN16/3X3/0.5LS_A 428,3044 r270 top locked value=ADCLK944
U5 "IC_MIC2544-1YMM_MSOP-8" SM/MSOP8_A 2481,91 r90 top locked value=MIC2544-1YMM
U6 "IC_5P49V5935_LGA-24" SM/LGA24/4X4/0.5LS_A 2205,1793 r180 top locked value=5P49V5935B000LTGI
U7 "IC_FIN1019MTCX_TSSOP-14" SM/TSSOP14_5X6.4MM_A 3009,1863 r270 top locked value=FIN1019MTCX
U8 "IC_IP4220CZ6_TSOP-6" SM/TSOP-6_A 3490,2021 r90 top locked value=IP4220CZ6
U9 "MODULE_JTAG-SMT3-NC_18P" SM/MODULE/DIGILENT/JTAG-SMT3 3975,765 r90 top locked value=JTAG-SMT3-NC
U10 "IC_TXS0108_TSSOP-20" SM/TSSOP20_6.5X6.4MM 807,1206 r90 top locked value=TXS0108EPW
U11 "IC_TXS0108_TSSOP-20" SM/TSSOP20_6.5X6.4MM 807,836 r90 top locked value=TXS0108EPW
U12 "TVS_CDSOT23_SOT23-6_C" SM/SOT23-6_C 3824.5,353 r0 top locked value=CDSOT23-SR208
U13 "REG_ADP3338_SOT223-3" SM/SOT223-3_B 2457,3069 r0 top value=ADP3338
U14 "REG_ADP334_DFN-8" SM/DFN8/3x3MM_B 564,3336 r270 top locked value=ADP3334
U15 "REG_ADP334_DFN-8" SM/DFN8/3x3MM_B 2949,2184 r90 top locked value=ADP3334
U16 "REG_ADP334_DFN-8" SM/DFN8/3x3MM_B 2020,3176 r0 bottom locked value=ADP3334
U17 "REG_ADP334_DFN-8" SM/DFN8/3x3MM_B 1766,3176 r0 bottom locked value=ADP3334
U18 "REG_TPS54561_WSON-10" SM/WSON10/4x4MM_A 3365,3435 r90 top value=TPS54561DPRR

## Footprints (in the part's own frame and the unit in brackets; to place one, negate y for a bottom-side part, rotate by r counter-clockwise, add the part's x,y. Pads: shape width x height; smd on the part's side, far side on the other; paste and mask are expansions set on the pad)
CON/100SP/1X3P [mil] "Based on Sullins .100\" breakaway series connectors"
  rect 70x70 hole 43 mask+4: 1(0,0)
  round 70 hole 43 mask+4: 2(100,0) 3(200,0)
  silkscreen extent -60,-60 260,80, body extent -50,-50 250,50, height 336
CON/100SP/2X7P/VT/038_A [mil] "2 x 7 header, vertical, no shroud"
  rect 70x70 hole 38: 1(-300,-50)
  round 70 hole 38: 2(-300,50) 3(-200,-50) 4(-200,50) 5(-100,-50) 6(-100,50) 7(0,-50) 8(0,50) 9(100,-50) 10(100,50) 11(200,-50) 12(200,50) 13(300,-50) 14(300,50)
  silkscreen extent -360,-135 360,110, body extent -350,-100 350,100, height 330
CON/100SP/2X13P/038_A [mil]
  rect 70x70 hole 38: 1(0,0)
  round 70 hole 38: 2(0,100) 3(100,0) 4(100,100) 5(200,0) 6(200,100) 7(300,0) 8(300,100) 9(400,0) 10(400,100) 11(500,0) 12(500,100) 13(600,0) 14(600,100) 15(700,0) 16(700,100) 17(800,0) 18(800,100) 19(900,0) 20(900,100) 21(1000,0) 22(1000,100) 23(1100,0) 24(1100,100) 25(1200,0) 26(1200,100)
  silkscreen extent -50,-100 1250,150
CON/MLX/0022112032/3P [mil] "Based on Molex  KK 100 series connector"
  rect 70x70 hole 43 mask+4: 1(0,0)
  round 70 hole 43 mask+4: 2(100,0) 3(200,0)
  silkscreen extent -60,-162 260,135, body extent -47,-128 247,122, height 422
CON/RJ45/L829-1J1T-43 [mil] "1 Port RJ45 Magjack Connector Through Hole 10/100/1000 Base-T, AutoMDIX"
  round 94 hole 62: 0(-146,260) 0(546,260)
  round 62 hole 41: 1(0,0) 2(80,0) 3(160,0) 4(240,0) 5(320,0) 6(400,0) 7(-40,-100) 8(40,-100) 9(120,-100) 10(280,-100) 11(360,-100) 12(440,-100)
  round 75 hole 50: 13(-96,510) 14(-96,610) 15(496,410) 16(496,510) 17(496,610)
  round 0 hole 130 unplated: ""(10,260) ""(390,260)
  silkscreen extent -157,-175 558,810, body extent -201,-167 601,800, height 494
CON/SAMTEC/SSW/2X6/RA_A/PMOD [mm] "PMOD Pin Assignments 12 Position Receptacle Connector  Through Hole, Right Angle"
  round 1.55 hole 1.04: 1(6.35,1.27) 2(3.81,1.27) 3(1.27,1.27) 4(-1.27,1.27) 5(-3.81,1.27) 6(-6.35,1.27) 7(6.35,-1.27) 8(3.81,-1.27) 9(1.27,-1.27) 10(-1.27,-1.27) 11(-3.81,-1.27) 12(-6.35,-1.27)
  silkscreen extent -8.1,-10.26 8.03,2.84, body extent -7.87,-11.3 7.87,1.47, height 5.02
CON/TE/2129320-3 [mil] "CONN RCP MINI DISPLAYPORT 20P RA"
  oval 55.43x110.87 hole 35.43 slot 92.52 at 90 deg: 0(-216.54,46.26) 0(216.54,46.26)
  oval 47.56x95.12 hole 27.56 slot 68.5 at 90 deg: 0(-204.72,-170.28) 0(204.72,-170.28)
  round 30 hole 22: 1(-106.3,6.89) 2(-106.3,138.78) 3(-88.58,38.39) 4(-88.58,170.28) 5(-53.15,38.39) 6(-53.15,170.28) 7(-35.43,6.89) 8(-35.43,138.78) 9(-17.72,38.39) 10(-17.72,170.28) 11(17.72,38.39) 12(17.72,170.28) 13(35.43,6.89) 14(35.43,138.78) 15(53.15,38.39) 16(53.15,170.28) 17(88.58,38.39) 18(88.58,170.28) 19(106.3,6.89) 20(106.3,138.78)
  round 39.37 hole 40 unplated: ""(-187.01,170.28) ""(187.01,170.28)
  silkscreen extent -233,-304 234,199, body extent -224,-308 224,190, height 186
CON/WURTH/694106301002 [mil] "Wurth DC power jack, 2.1mm pin, right angle"
  oval 158x71 hole 31 slot 118 at 0 deg: 1(0,0) 2(0,228)
  oval 71x158 hole 31 slot 118 at 90 deg: 3(-189,118)
  silkscreen extent -195,-45 170,540, body extent -197,-36 177,535, height 421
MTG125/78 [mil]
  round 125 hole 78 mask+4: 1(0,0)
MTG220/120#1 [mil] "Hole size that works with a #4 Pan Head screw"
  round 220 hole 120 mask+4: 1(0,-1000)
MTG220/120#2 [mil] "Hole size that works with a #4 Pan Head screw"
  round 220 hole 120 mask+4: 1(0,0)
MTG220/120#3 [mil] "Hole size that works with a #4 Pan Head screw"
  round 220 hole 120 mask+4: 1(100,0)
SM/0402 [mil]
  rect 22x20 smd mask+3: 1(-20,0) 2(20,0)
SM/0402/CAP [mil]
  rect 22x20 smd mask+3: 1(-20,0) 2(20,0)
  body extent -20,-10 20,10, height 20
SM/0402/RES [mil]
  rect 20x20 smd mask+3: 1(-20,0) 2(20,0)
  body extent -20,-10 20,10, height 18
SM/0603 [mil]
  rect 36x32 smd mask+3: 1(-30,0) 2(30,0)
  body extent -31,-16 32,16, height 31
SM/0603/CAP [mil]
  rect 36x32 smd mask+3: 1(-30,0) 2(30,0)
  silkscreen extent -3,-20 3,20, body extent -31,-17 31,17, height 28
SM/0805/CAP [mil]
  rect 45x50 smd mask+3: 1(-40,0) 2(40,0)
  silkscreen extent -8,-27 8,25, body extent -39,-25 39,25, height 54
SM/0805/RES [mil]
  rect 45x50 smd mask+3: 1(-40,0) 2(40,0)
  silkscreen extent -8,-25 8,25, body extent -45,-27 45,27, height 29
SM/CAP/TANT-D_A [mil]
  rect 100x110 smd mask+3: 1(-125,0) 2(125,0)
  silkscreen extent -192,-90 190,90
SM/CON/JAE/WR-40SB-VFH30-N1 [mil] "CONN RECEPTICAL 40POS SMD GOLD 0.5mm"
  rect 20x80 smd: 01(-192,-86) 02(-192,86) 39(192,-86) 40(192,86)
  rect 10x80 smd: 03(-167.32,-86) 04(-167.32,86) 05(-147.64,-86) 06(-147.64,86) 07(-127.95,-86) 08(-127.95,86) 09(-108.27,-86) 10(-108.27,86) 11(-88.58,-86) 12(-88.58,86) 13(-68.9,-86) 14(-68.9,86) 15(-49.21,-86) 16(-49.21,86) 17(-29.53,-86) 18(-29.53,86) 19(-9.84,-86) 20(-9.84,86) 21(9.84,-86) 22(9.84,86) 23(29.53,-86) 24(29.53,86) 25(49.21,-86) 26(49.21,86) 27(68.9,-86) 28(68.9,86) 29(88.58,-86) 30(88.58,86) 31(108.27,-86) 32(108.27,86) 33(127.95,-86) 34(127.95,86) 35(147.64,-86) 36(147.64,86) 37(167.32,-86) 38(167.32,86)
  round 0 hole 25.59 unplated mask+6: " "(-216.54,-41.34) ""(216.54,41.34)
  silkscreen extent -236,-145 236,99, body extent -226,-98 226,98, height 246
SM/CON/JAE/WR-120S-VFH30-N1 [mil] "CONN RECEPTICAL 120POS SMD GOLD 0.5mm"
  rect 10x80 smd: 01(-580.71,-86.61) 02(-580.71,86.61) 03(-561.02,-86.61) 04(-561.02,86.61) 05(-541.34,-86.61) 06(-541.34,86.61) 07(-521.65,-86.61) 08(-521.65,86.61) 09(-501.97,-86.61) 10(-501.97,86.61) 11(-482.28,-86.61) 12(-482.28,86.61) 13(-462.6,-86.61) 14(-462.6,86.61) 15(-442.91,-86.61) 16(-442.91,86.61) 17(-423.23,-86.61) 18(-423.23,86.61) 19(-403.54,-86.61) 20(-403.54,86.61) 21(-383.86,-86.61) 22(-383.86,86.61) 23(-364.17,-86.61) 24(-364.17,86.61) 25(-344.49,-86.61) 26(-344.49,86.61) 27(-324.8,-86.61) 28(-324.8,86.61) 29(-305.12,-86.61) 30(-305.12,86.61) 31(-285.43,-86.61) 32(-285.43,86.61) 33(-265.75,-86.61) 34(-265.75,86.61) 35(-246.06,-86.61) 36(-246.06,86.61) 37(-226.38,-86.61) 38(-226.38,86.61) 39(-206.69,-86.61) 40(-206.69,86.61) 41(-187.01,-86.61) 42(-187.01,86.61) 43(-167.32,-86.61) 44(-167.32,86.61) 45(-147.64,-86.61) 46(-147.64,86.61) 47(-127.95,-86.61) 48(-127.95,86.61) 49(-108.27,-86.61) 50(-108.27,86.61) 51(-88.58,-86.61) 52(-88.58,86.61) 53(-68.9,-86.61) 54(-68.9,86.61) 55(-49.21,-86.61) 56(-49.21,86.61) 57(-29.53,-86.61) 58(-29.53,86.61) 59(-9.84,-86.61) 60(-9.84,86.61) 61(9.84,-86.61) 62(9.84,86.61) 63(29.53,-86.61) 64(29.53,86.61) 65(49.21,-86.61) 66(49.21,86.61) 67(68.9,-86.61) 68(68.9,86.61) 69(88.58,-86.61) 70(88.58,86.61) 71(108.27,-86.61) 72(108.27,86.61) 73(127.95,-86.61) 74(127.95,86.61) 75(147.64,-86.61) 76(147.64,86.61) 77(167.32,-86.61) 78(167.32,86.61) 79(187.01,-86.61) 80(187.01,86.61) 81(206.69,-86.61) 82(206.69,86.61) 83(226.38,-86.61) 84(226.38,86.61) 85(246.06,-86.61) 86(246.06,86.61) 87(265.75,-86.61) 88(265.75,86.61) 89(285.43,-86.61) 90(285.43,86.61) 91(305.12,-86.61) 92(305.12,86.61) 93(324.8,-86.61) 94(324.8,86.61) 95(344.49,-86.61) 96(344.49,86.61) 97(364.17,-86.61) 98(364.17,86.61) 99(383.86,-86.61) 100(383.86,86.61) 101(403.54,-86.61) 102(403.54,86.61) 103(423.23,-86.61) 104(423.23,86.61) 105(442.91,-86.61) 106(442.91,86.61) 107(462.6,-86.61) 108(462.6,86.61) 109(482.28,-86.61) 110(482.28,86.61) 111(501.97,-86.61) 112(501.97,86.61) 113(521.65,-86.61) 114(521.65,86.61) 115(541.34,-86.61) 116(541.34,86.61) 117(561.02,-86.61) 118(561.02,86.61) 119(580.71,-86.61) 120(580.71,86.61)
  rect 20x80 smd: M1(-605.31,-86.61) M2(-605.31,86.61) M3(605.31,-86.61) M4(605.31,86.61)
  silkscreen extent -627,-145 628,98, body extent -620,-98 620,98, height 246
SM/CON/MICRO_SD-CARD/HOLDER [mil] "HIROSE MICRO SD CARD HOLDER"
  rect 28x79 smd mask+3: 1(122,-250) 2(79,-250) 3(35,-250) 4(-8,-250) 5(-51,-250) 6(-95,-250) 7(-138,-250) 8(-181,-250)
  rect 106x55 smd mask+3: 9(67,248) M-3(-126,248)
  rect 59x102 smd mask+3: M-1(264,-226)
  rect 39x102 smd mask+3: M-2(-264,-226)
  rect 47x47 smd mask+3: M-4(187,252)
  Top Layer keep-out region: -275.59,-169 -251.97,-169 -251.97,-29.53 -275.59,-29.53
  Top Layer keep-out region: 263.78,-169 287.4,-169 287.4,-33.46 263.78,-33.46
  Top Layer keep-out region: -202.76,64.94 143.7,64.94 143.7,163.36 -202.76,163.36
  silkscreen extent -295,-344 305,289, body extent -268,-277 275,278, height 78
SM/CON/MLX/0878321420 [mil] "Connector Header Surface Mount 14 position 0.079\" (2.00mm)"
  rect 41x109 smd: 1(-236,-84) 2(-236,84) 3(-157,-84) 4(-157,84) 5(-78,-84) 6(-78,84) 7(0,-84) 8(0,84) 9(78,-84) 10(78,84) 11(157,-84) 12(157,84) 13(236,-84) 14(236,84)
  round 19.68 hole 40 unplated: MH1(-197,0) MH2(197,0)
  silkscreen extent -328,-165 327,124, body extent -328,-124 327,124, height 299
SM/CON/MLX/SATA/0470804002 [mil] "CONN SATA PLUG 7POS SLD R/A SMD"
  round 91.54 hole 61.02: 0(-400.75,-93) 0(100.75,-93)
  rect 36x80 smd: 1(0,0) 2(-50,0) 3(-100,0) 4(-150,0) 5(-200,0) 6(-250,0) 7(-300,0)
  silkscreen extent -530,-420 190,60, body extent -515,-424 176,31, height 229
SM/CON/RF/SMA/BRD-EDGE_C [mil] "SMA sized jacks, mounted to board edge, .250\" wide"
  rect 40x180 smd mask+3: 1(0,-105)
  rect 80x180 smd mask+3: 2(-110,-105) 2(110,-105)
  rect 80x180 smd far side mask+3: 2(-110,-105) 2(110,-105)
  silkscreen extent -170,-210 170,-15, body extent -118,-167 118,368, height 134
SM/CON/RF/SMPM/VERT_A [mil] "Based off of Amphenol 925-144J-51PT"
  rect 17x70 smd: 1(0,-90)
  round 20 hole 10 mask+2: 2(-78.74,0) 2(0,78.74) 2(78.74,0)
  round 20 hole 10 mask+6: 2(-68,-42) 2(-68,40) 2(-40,67.5) 2(40,67.5) 2(68,-42) 2(68,40)
  rect 55.12x19.68 smd: 2(-0.5,65.5)
  round 0 hole 41 unplated mask+6: " "(0,0)
  Top Layer region: -84,-81 -84,83.5 84,83.5 84,-81 27,-81 27,-41.93 43.96,-23.3 49.6,1.25 42.45,25.4 24.36,42.94 0,49.33 -24.37,42.94 -42.45,25.4 -49.6,1.25 -43.97,-23.31 -27,-41.93 -27,-41.93 -27,-81
  Top Layer pour cut-out: -82.68,-81 82.68,-81 82.68,82.68 -82.68,82.68
  silkscreen extent -96,-81 96,81, body extent -78,-113 78,78, height 107
"SM/CON/USB3.1/MICRO B" [mil] "USB3.1 Micro-B, based off of Amphenol GSB443133HR"
  rect 16x54 smd mask+3: 1(0,0) 2(25,0) 3(51,0) 4(77,0) 5(102,0) 6(263.78,0) 7(288.78,0) 8(314.78,0) 9(340.78,0) 10(365.78,0)
  rect 75x75 smd mask+3: 11(-108,-105) 12(3,-105) 13(99,-105) 14(210,-105) 15(308,-105)
  rect 90.55x75 smd mask+3: 16(409.57,-105)
  silkscreen extent -159,-153 468,55, body extent -122,-210 435,15, height 106
"SM/CON/USB/MICRO B RA" [mil] "USB RA CONNECTOR - BASED ON MOLEX 1051640001"
  rect 54x18 smd mask+3: 1(105,-51) 2(105,-26) 3(105,0) 4(105,26) 5(105,51)
  rect 75x35 smd mask+3: SH(0,47) SH(0,-47)
  rect 62x58 smd mask+3: SH(101,98) SH(101,-98)
  oval 83x55 hole 24 slot 52 at 0 deg mask+3: TH(0,155) TH(0,-155)
  silkscreen extent 90,-170 150,170, body extent -85,-161 118,161, height 97
SM/DFN8/2X2MM_E [mil] "DFN-8 with .9mm x 1.7mm slug included GND vias"
  rect 12x26 smd mask+2.5: 1(-30,-37) 2(-10,-37) 3(10,-37) 4(30,-37) 5(30,37) 6(10,37) 7(-10,37) 8(-30,37)
  round 20 hole 10 mask+3: 9(-22,0) 9(0,0) 9(22,0)
  rect 66.93x27.56 smd mask+2.5: 9(0,0)
  silkscreen extent -45,-45 45,45, body extent -40,-40 40,40, height 33
SM/DFN8/3x3MM_B [mil]
  rect 10x28 smd paste+0 mask+3: 1(-30,-55) 2(-10,-55) 3(10,-55) 4(30,-55) 5(30,55) 6(10,55) 7(-10,55) 8(-30,55)
  rect 90x58 smd paste-5 mask+3: 9(0,0)
  silkscreen extent -60,-87 60,60, body extent -59,-59 59,59, height 31
SM/DFN10/2.5X1MM_A [mil] "TI DQA (R-PSON-N10)"
  rect 12x22 smd paste+0 mask+2: 1(-39.37,-15.5) 2(-19.69,-15.5) 4(19.69,-15.5) 5(39.37,-15.5) 6(39.37,15.5) 7(19.69,15.5) 9(-19.69,15.5) 10(-39.37,15.5)
  rect 15x22 smd paste+0 mask+2: 3(0,-15.5) 8(0,15.5)
  silkscreen extent -53,-39 53,24, body extent -49,-19 49,20, height 22
SM/DO-214AA/SMB_A [mil]
  rect 85x108 smd mask+3: 1(-85,0) 2(85,0)
  silkscreen extent -150,-80 145,80, body extent -104,-73 104,73, height 89
SM/IND/COILCRAFT/XAL4020 [mil] "XAL4020 shielded power inductor"
  rect 40x134 smd mask+3: 1(-45,0) 2(45,0)
  silkscreen extent -90,-90 90,90, body extent -80,-80 80,80, height 61
SM/IND/COILCRAFT/XAL7030 [mil] "XAL7030 Series High Current  Power Inductors"
  rect 70x256 smd mask+3: 1(-95,0) 2(95,0)
  silkscreen extent -160,-160 160,160, body extent -157,-157 157,158, height 121
SM/LED_0603 [mil]
  rect 35x35.43 smd mask+3: 1(-30,0) 2(30,0)
  silkscreen extent -60,-30 -30,30, body extent -33,-18 33,18, height 35
SM/LGA24/4X4/0.5LS_A [mil]
  rect 12x20 smd paste+0 mask+2: 1(-49,-72) 2(-30,-72) 3(-10,-72) 4(10,-72) 5(30,-72) 6(49,-72) 13(49,72) 14(30,72) 15(10,72) 16(-10,72) 17(-30,72) 18(-49,72)
  rect 20x12 smd paste+0 mask+2: 7(72,-49) 8(72,-30) 9(72,-10) 10(72,10) 11(72,30) 12(72,49) 19(-72,49) 20(-72,30) 21(-72,10) 22(-72,-10) 23(-72,-30) 24(-72,-49)
  rect 60x60 smd paste-5 mask+2: 25(0,0)
  silkscreen extent -87,-96 85,85, body extent -78,-78 78,78, height 60
SM/MODULE/DIGILENT/JTAG-SMT3 [mil] "JTAG-SMT3 Programming module for Xilinx FPGAs"
  rect 91x112 smd mask+3: 1(0,0) 2(157,0) 3(315,0) 4(473,0) 5(630,0) 10(630,784) 11(473,784) 12(315,784) 13(157,784) 14(0,784)
  rect 112x91 smd mask+3: 6(732,156) 7(732,313) 8(732,471) 9(732,628) 15(-102,628) 16(-102,471) 17(-102,313) 18(-102,156)
  silkscreen extent -146,-80 776,827, body extent -132,-31 764,815, height 102
SM/MSOP8_A [mil]
  rect 16x46 smd mask+3: 1(-38,-90) 2(-13,-90) 3(13,-90) 4(38,-90) 5(38,90) 6(13,90) 7(-13,90) 8(-38,90)
  silkscreen extent -65,-123 65,123, body extent -59,-99 59,98, height 39
SM/POWERPAK/VISHAY/SO-8 [mm] "Vishay PowerPAK"
  rect 0.635x1.27 smd: 1(-1.905,-1.335) 2(-0.635,-1.335) 3(0.635,-1.335) 4(1.905,-1.335)
  rect 1x1 smd paste-1 mask+0: 5(0,1.335)
  Top Layer region: -1.6,4.64 -1.6,3.93 -0.94,3.93 -0.94,4.64 -0.33,4.64 -0.33,3.93 0.33,3.93 0.33,4.64 0.94,4.64 0.94,3.93 1.6,3.93 1.6,4.64 2.21,4.64 2.21,3.62 1.955,3.62 1.955,0.12 -1.955,0.12 -1.955,3.62 -2.21,3.62 -2.21,4.64
  silkscreen extent -2.6,-2.44 2.58,3.09, body extent -2.46,-1.61 2.46,4.28, height 1.02
SM/QFN16/3X3/0.5LS_A [mil]
  rect 12x32 smd paste+0 mask+3: 1(-30,-58) 2(-10,-58) 3(10,-58) 4(30,-58) 9(30,58) 10(10,58) 11(-10,58) 12(-30,58)
  rect 32x12 smd paste+0 mask+3: 5(58,-30) 6(58,-10) 7(58,10) 8(58,30) 13(-58,30) 14(-58,10) 15(-58,-10) 16(-58,-30)
  rect 64x64 smd paste-3 mask+3: 17(0,0)
  silkscreen extent -67,-91 65,65, body extent -59,-59 59,59, height 35
SM/SOT3_A [mil]
  rect 13x14 smd: 1(0,0) 2(28,0) 3(14,46)
  silkscreen extent -16,-1 -16,0, body extent -6,3 33,43, height 20
SM/SOT23-6_C [mil] "SOT23-6"
  rect 24x48 smd: 1(38,50) 2(0,50) 3(-38,50) 4(-38,-50) 5(0,-50) 6(38,-50)
  silkscreen extent -58,-12 63,73, body extent -58,-55 58,55, height 51
SM/SOT23_A [mil]
  rect 36x50 smd mask+3: 1(-38,-43) 2(38,-43) 3(0,43)
  silkscreen extent -70,-15 70,65, body extent -58,-54 56,56, height 51
SM/SOT223-3_B [mil] "SOT-223/SC-73; 4 Leads; Body 6.7 x 7.3 mm, inc. leads (LxW max)"
  rect 43x84 smd mask+3: 1(-90,-120) 2(0,-120) 3(90,-120)
  rect 138x84 smd mask+3: 2(0,120)
  silkscreen extent -135,-65 136,65, body extent -128,-138 128,138, height 67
